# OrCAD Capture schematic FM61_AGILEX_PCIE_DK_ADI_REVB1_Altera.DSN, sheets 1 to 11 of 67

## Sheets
1 Title, Note, Rev. Hist: title: AgileX F-Series FPGA Dev Kit_ADI; rev: B1; note: M75579-100(100-0330692-B1)
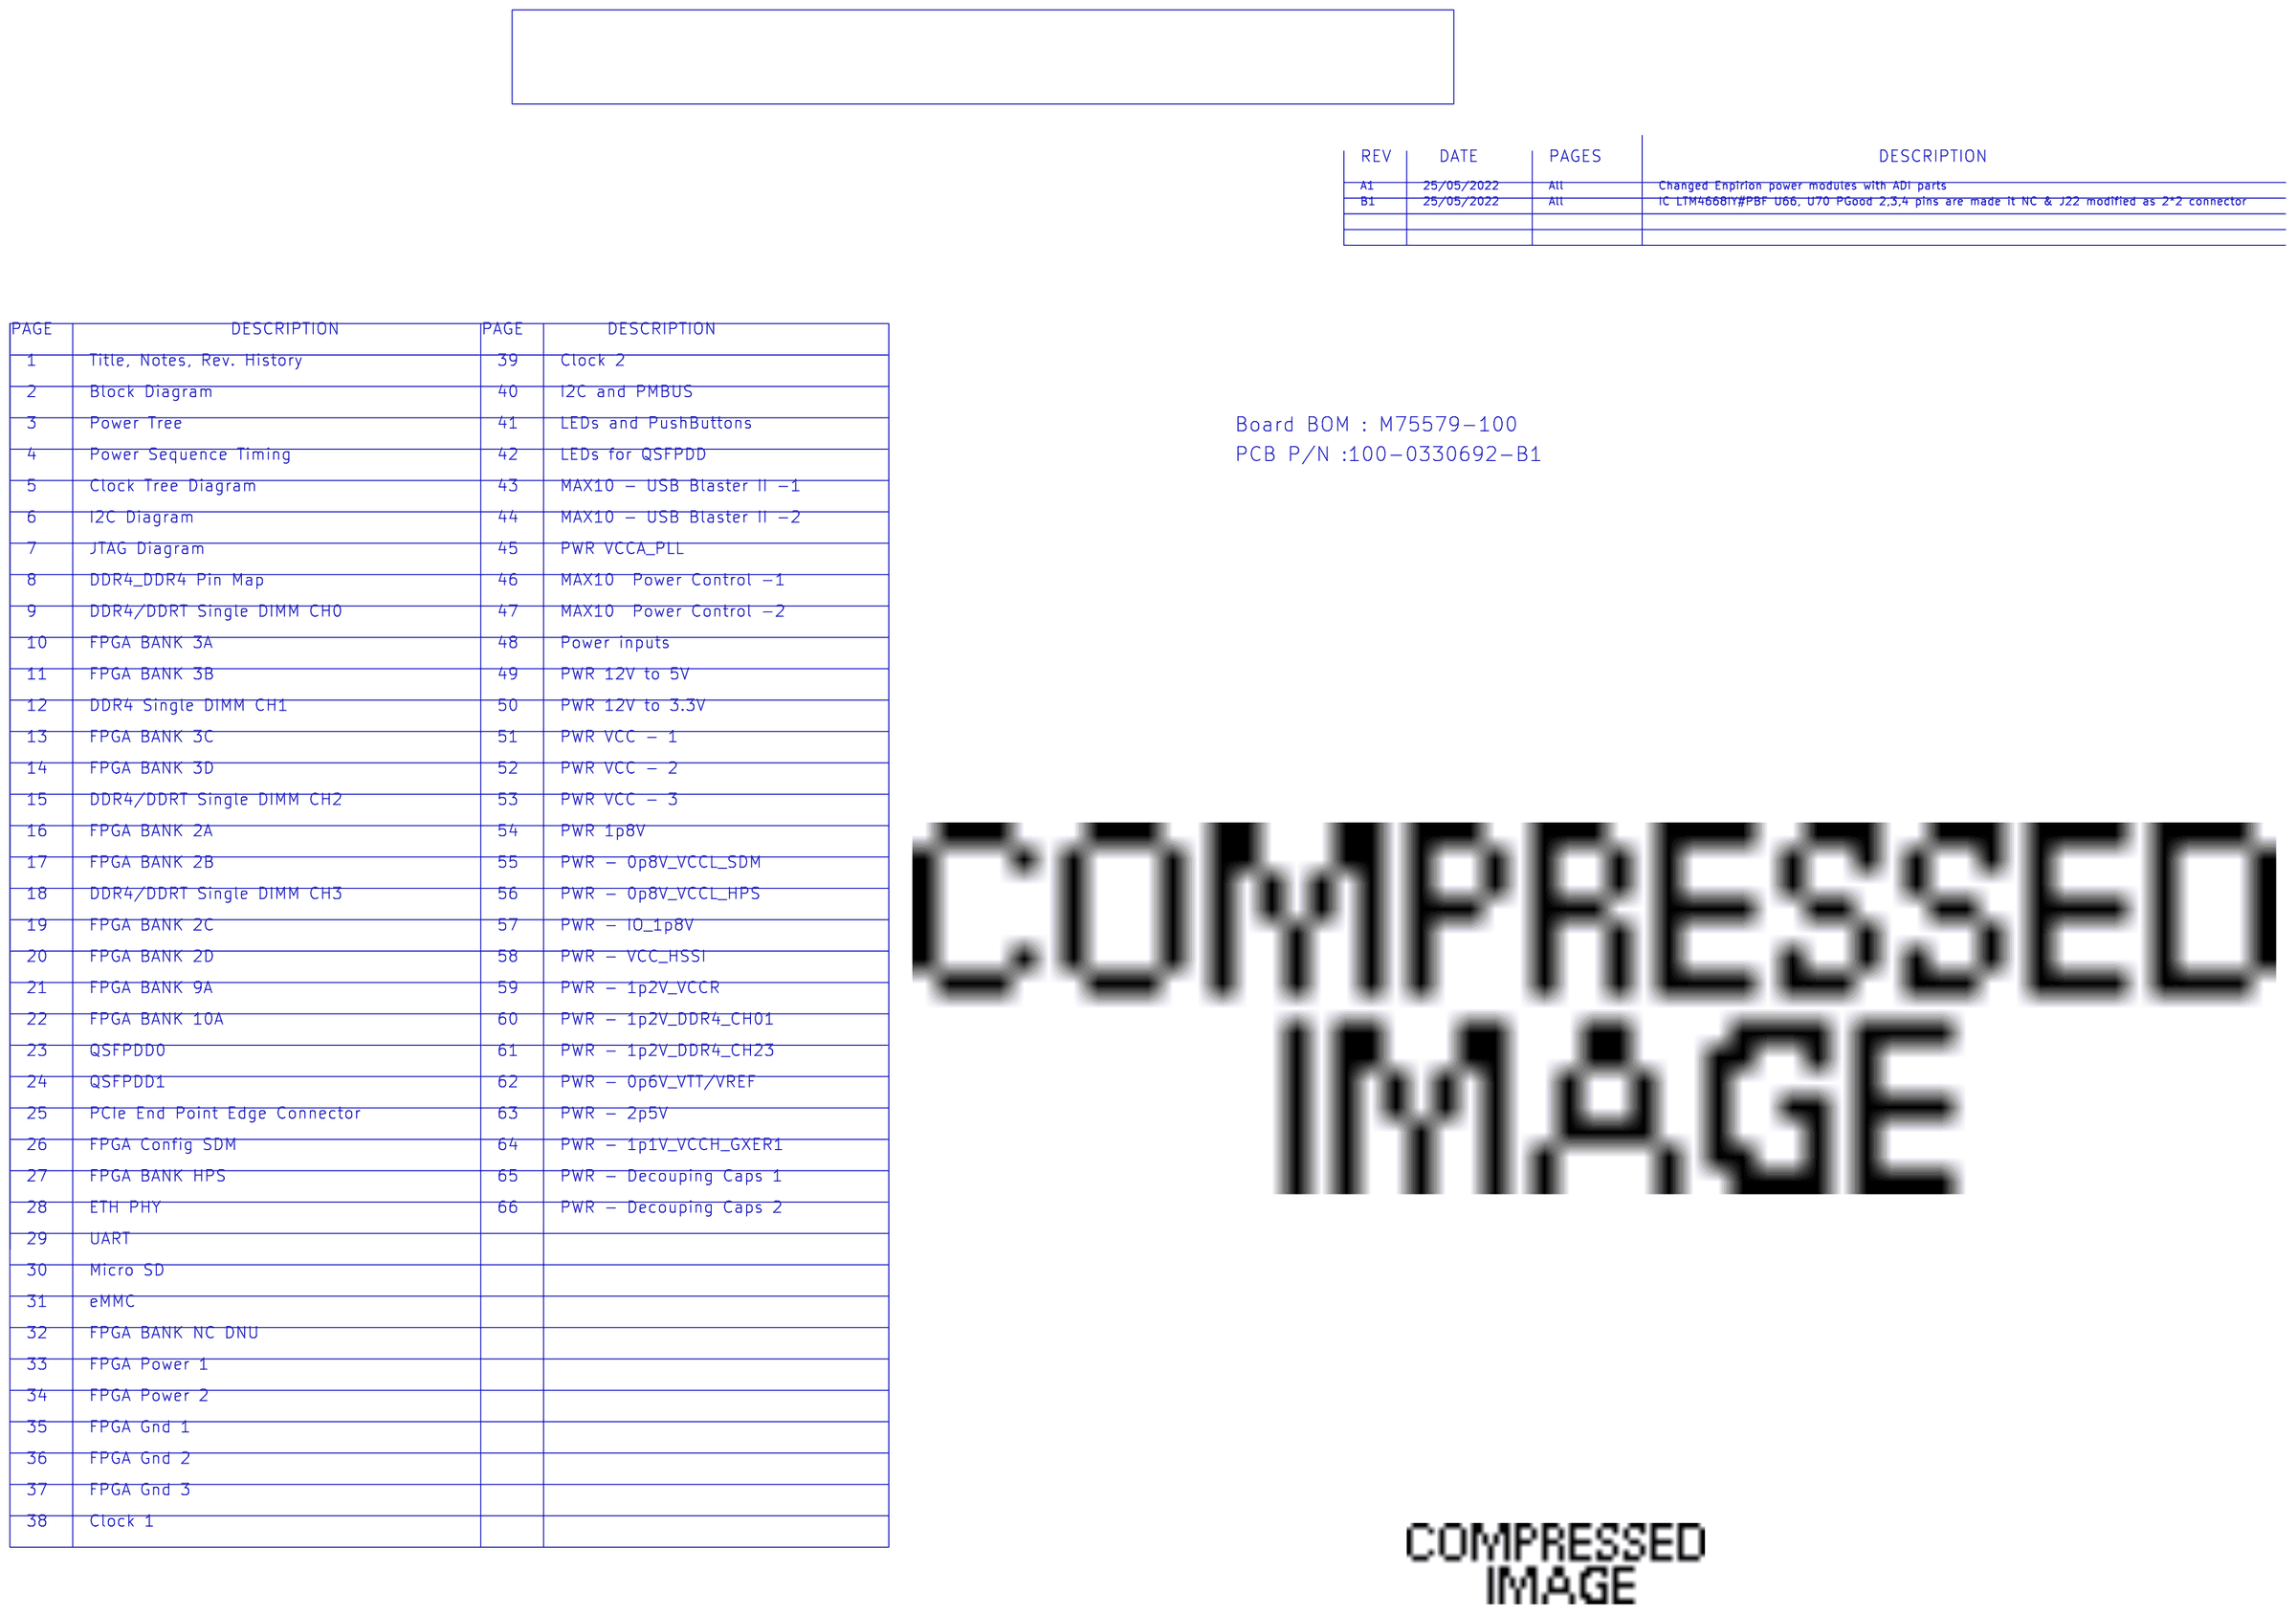
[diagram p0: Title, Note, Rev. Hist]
2 Block Diagram
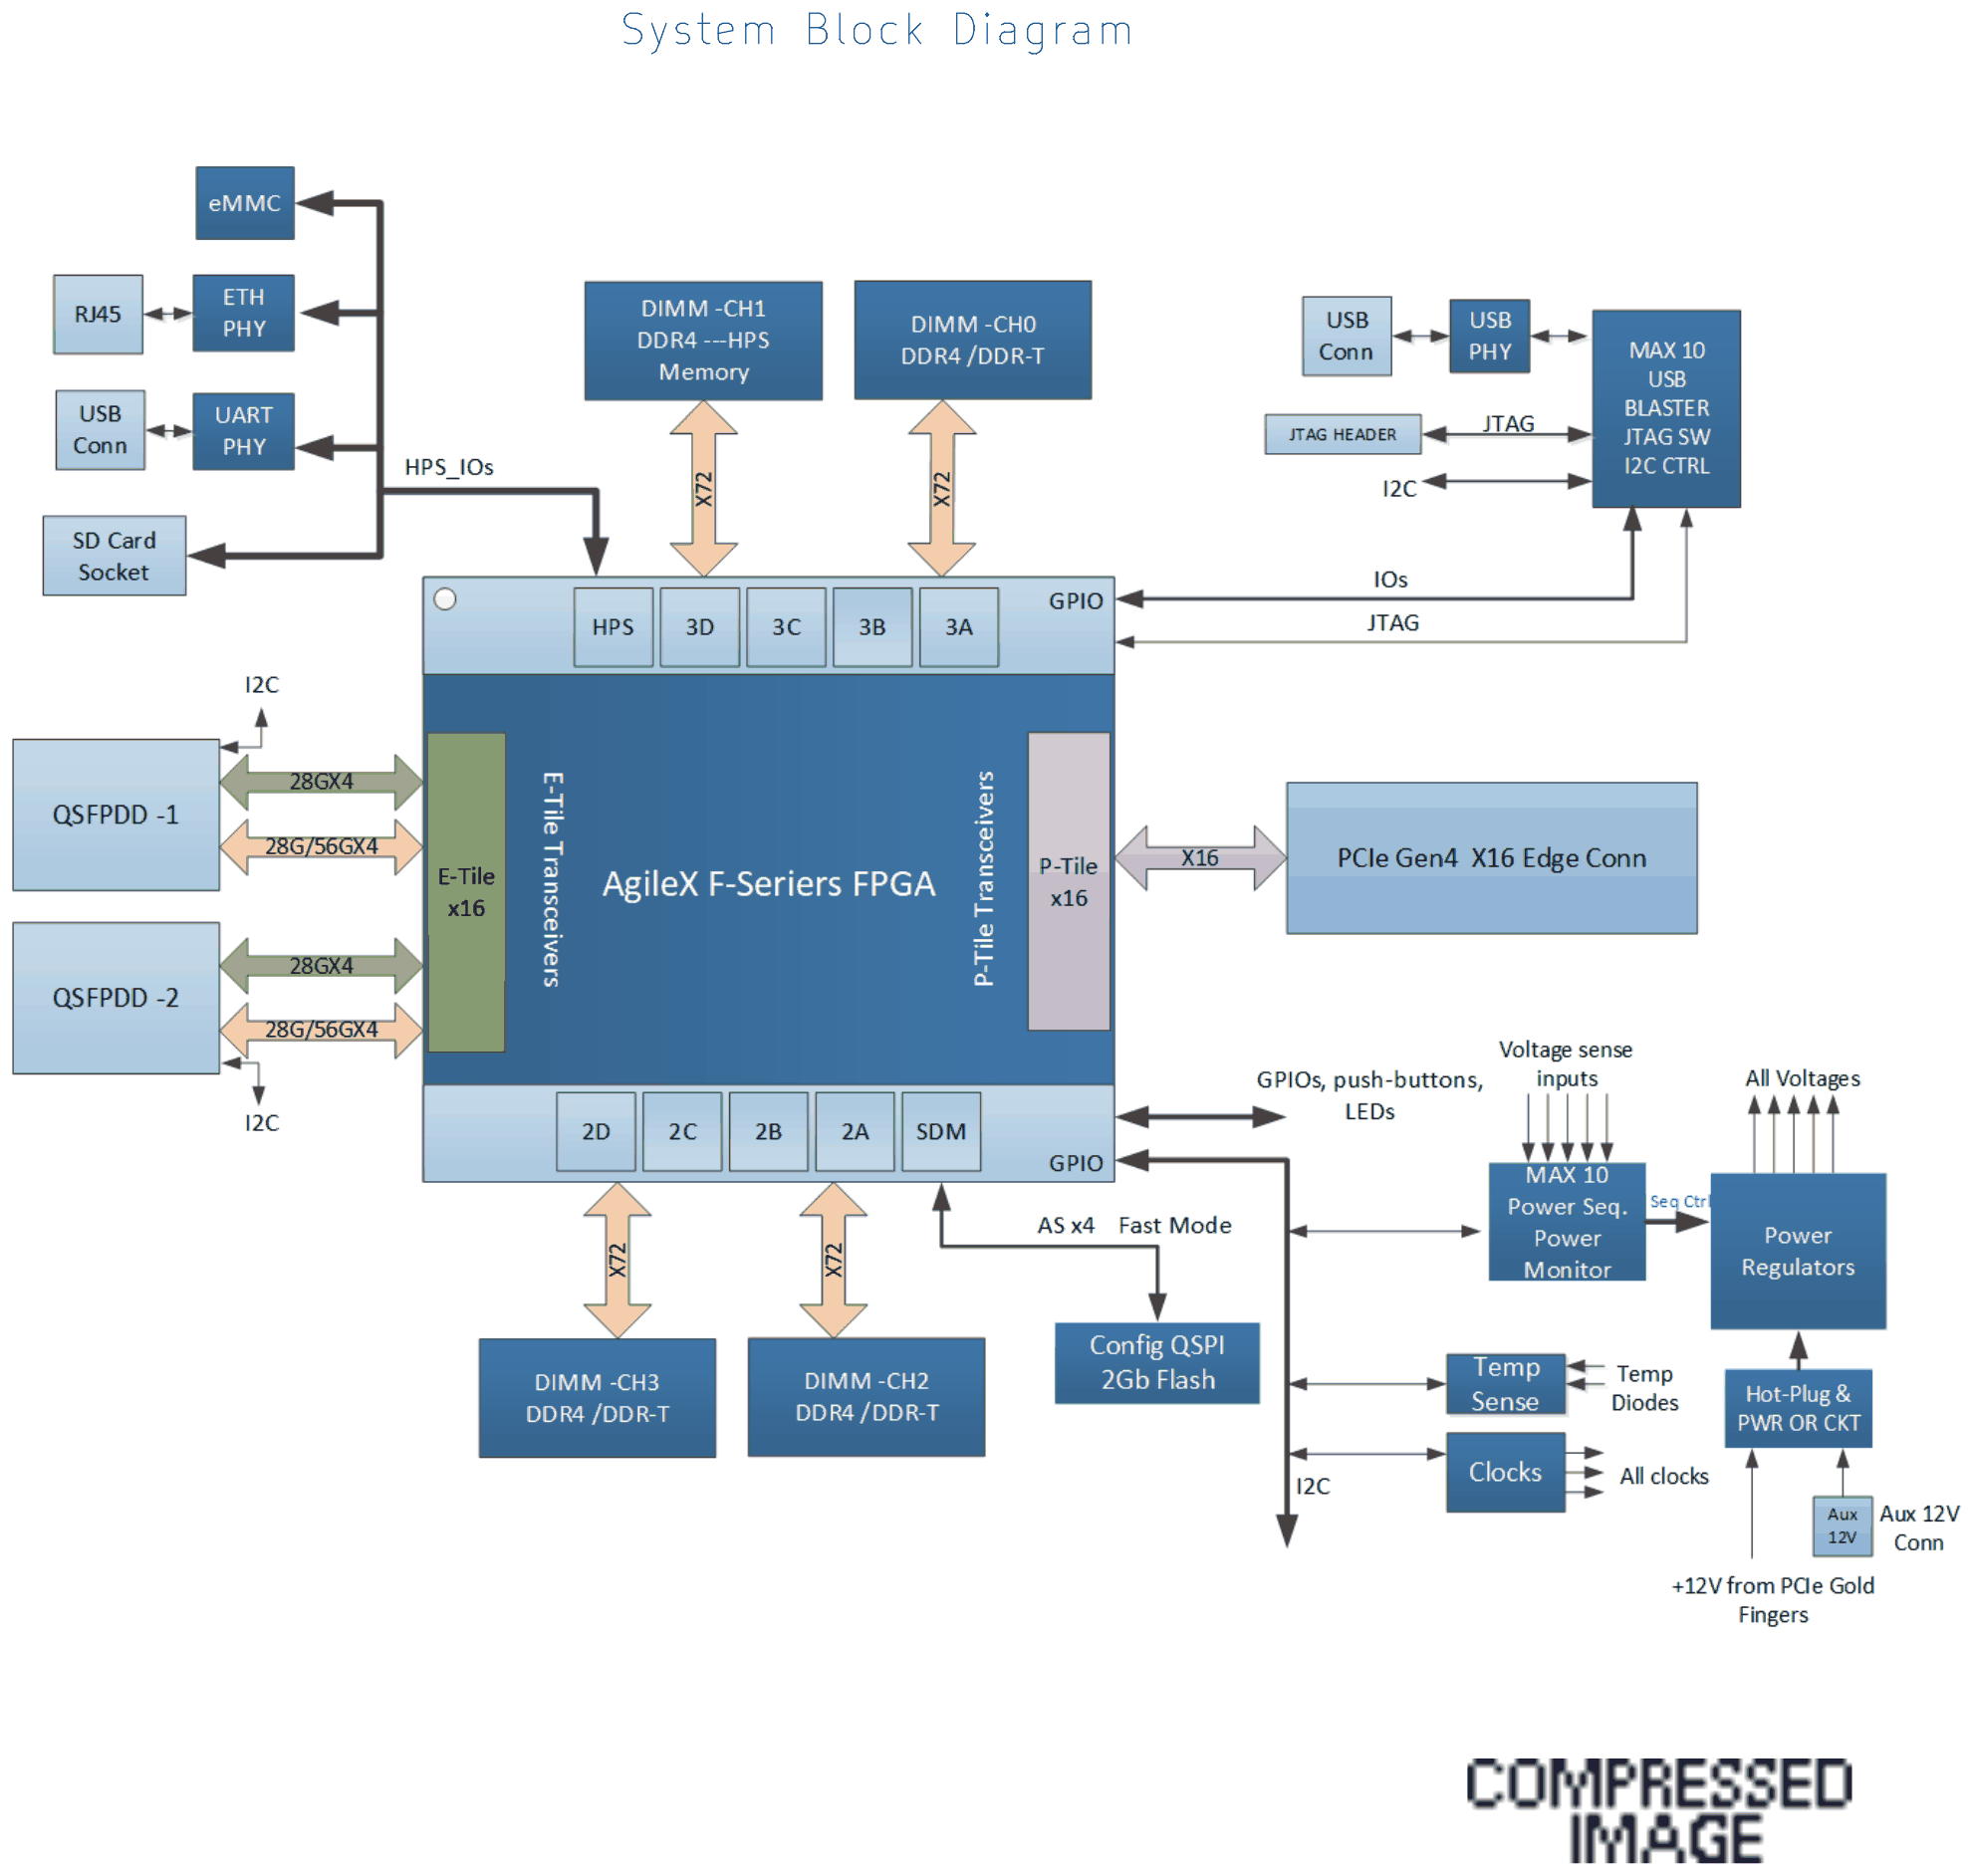
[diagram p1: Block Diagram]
3 Power Tree
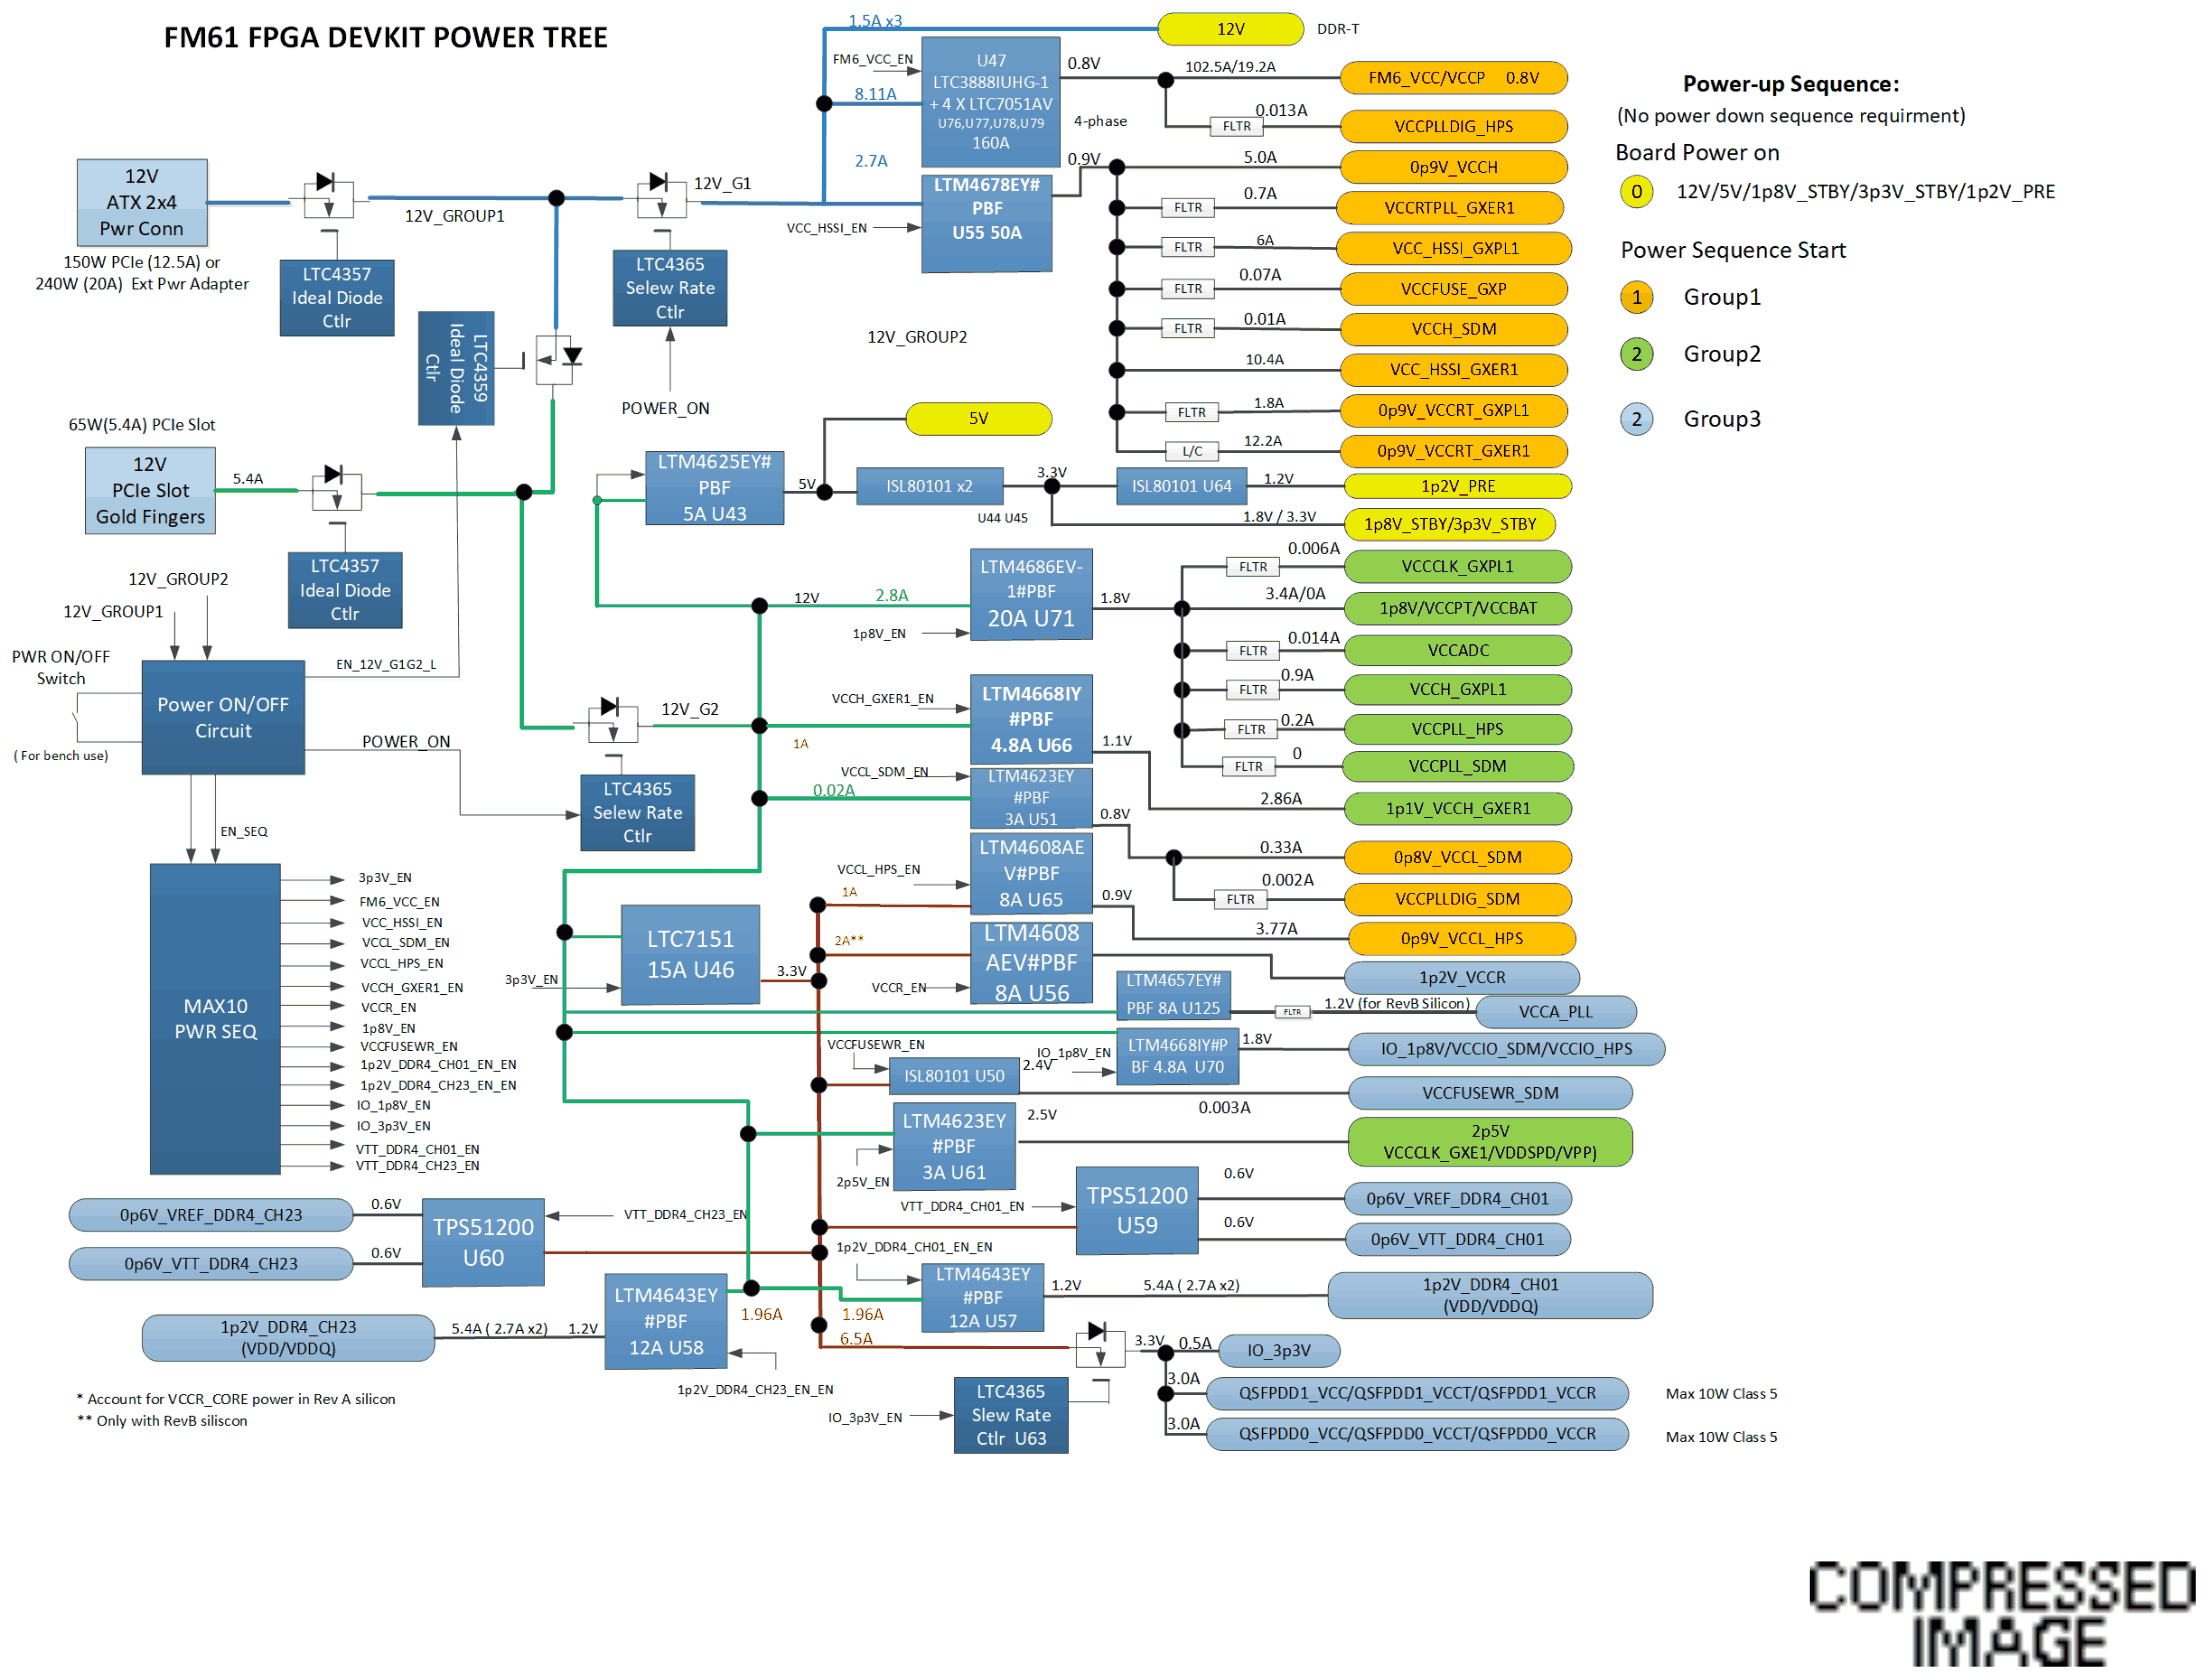
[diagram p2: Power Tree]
4 Power Sequence Timing
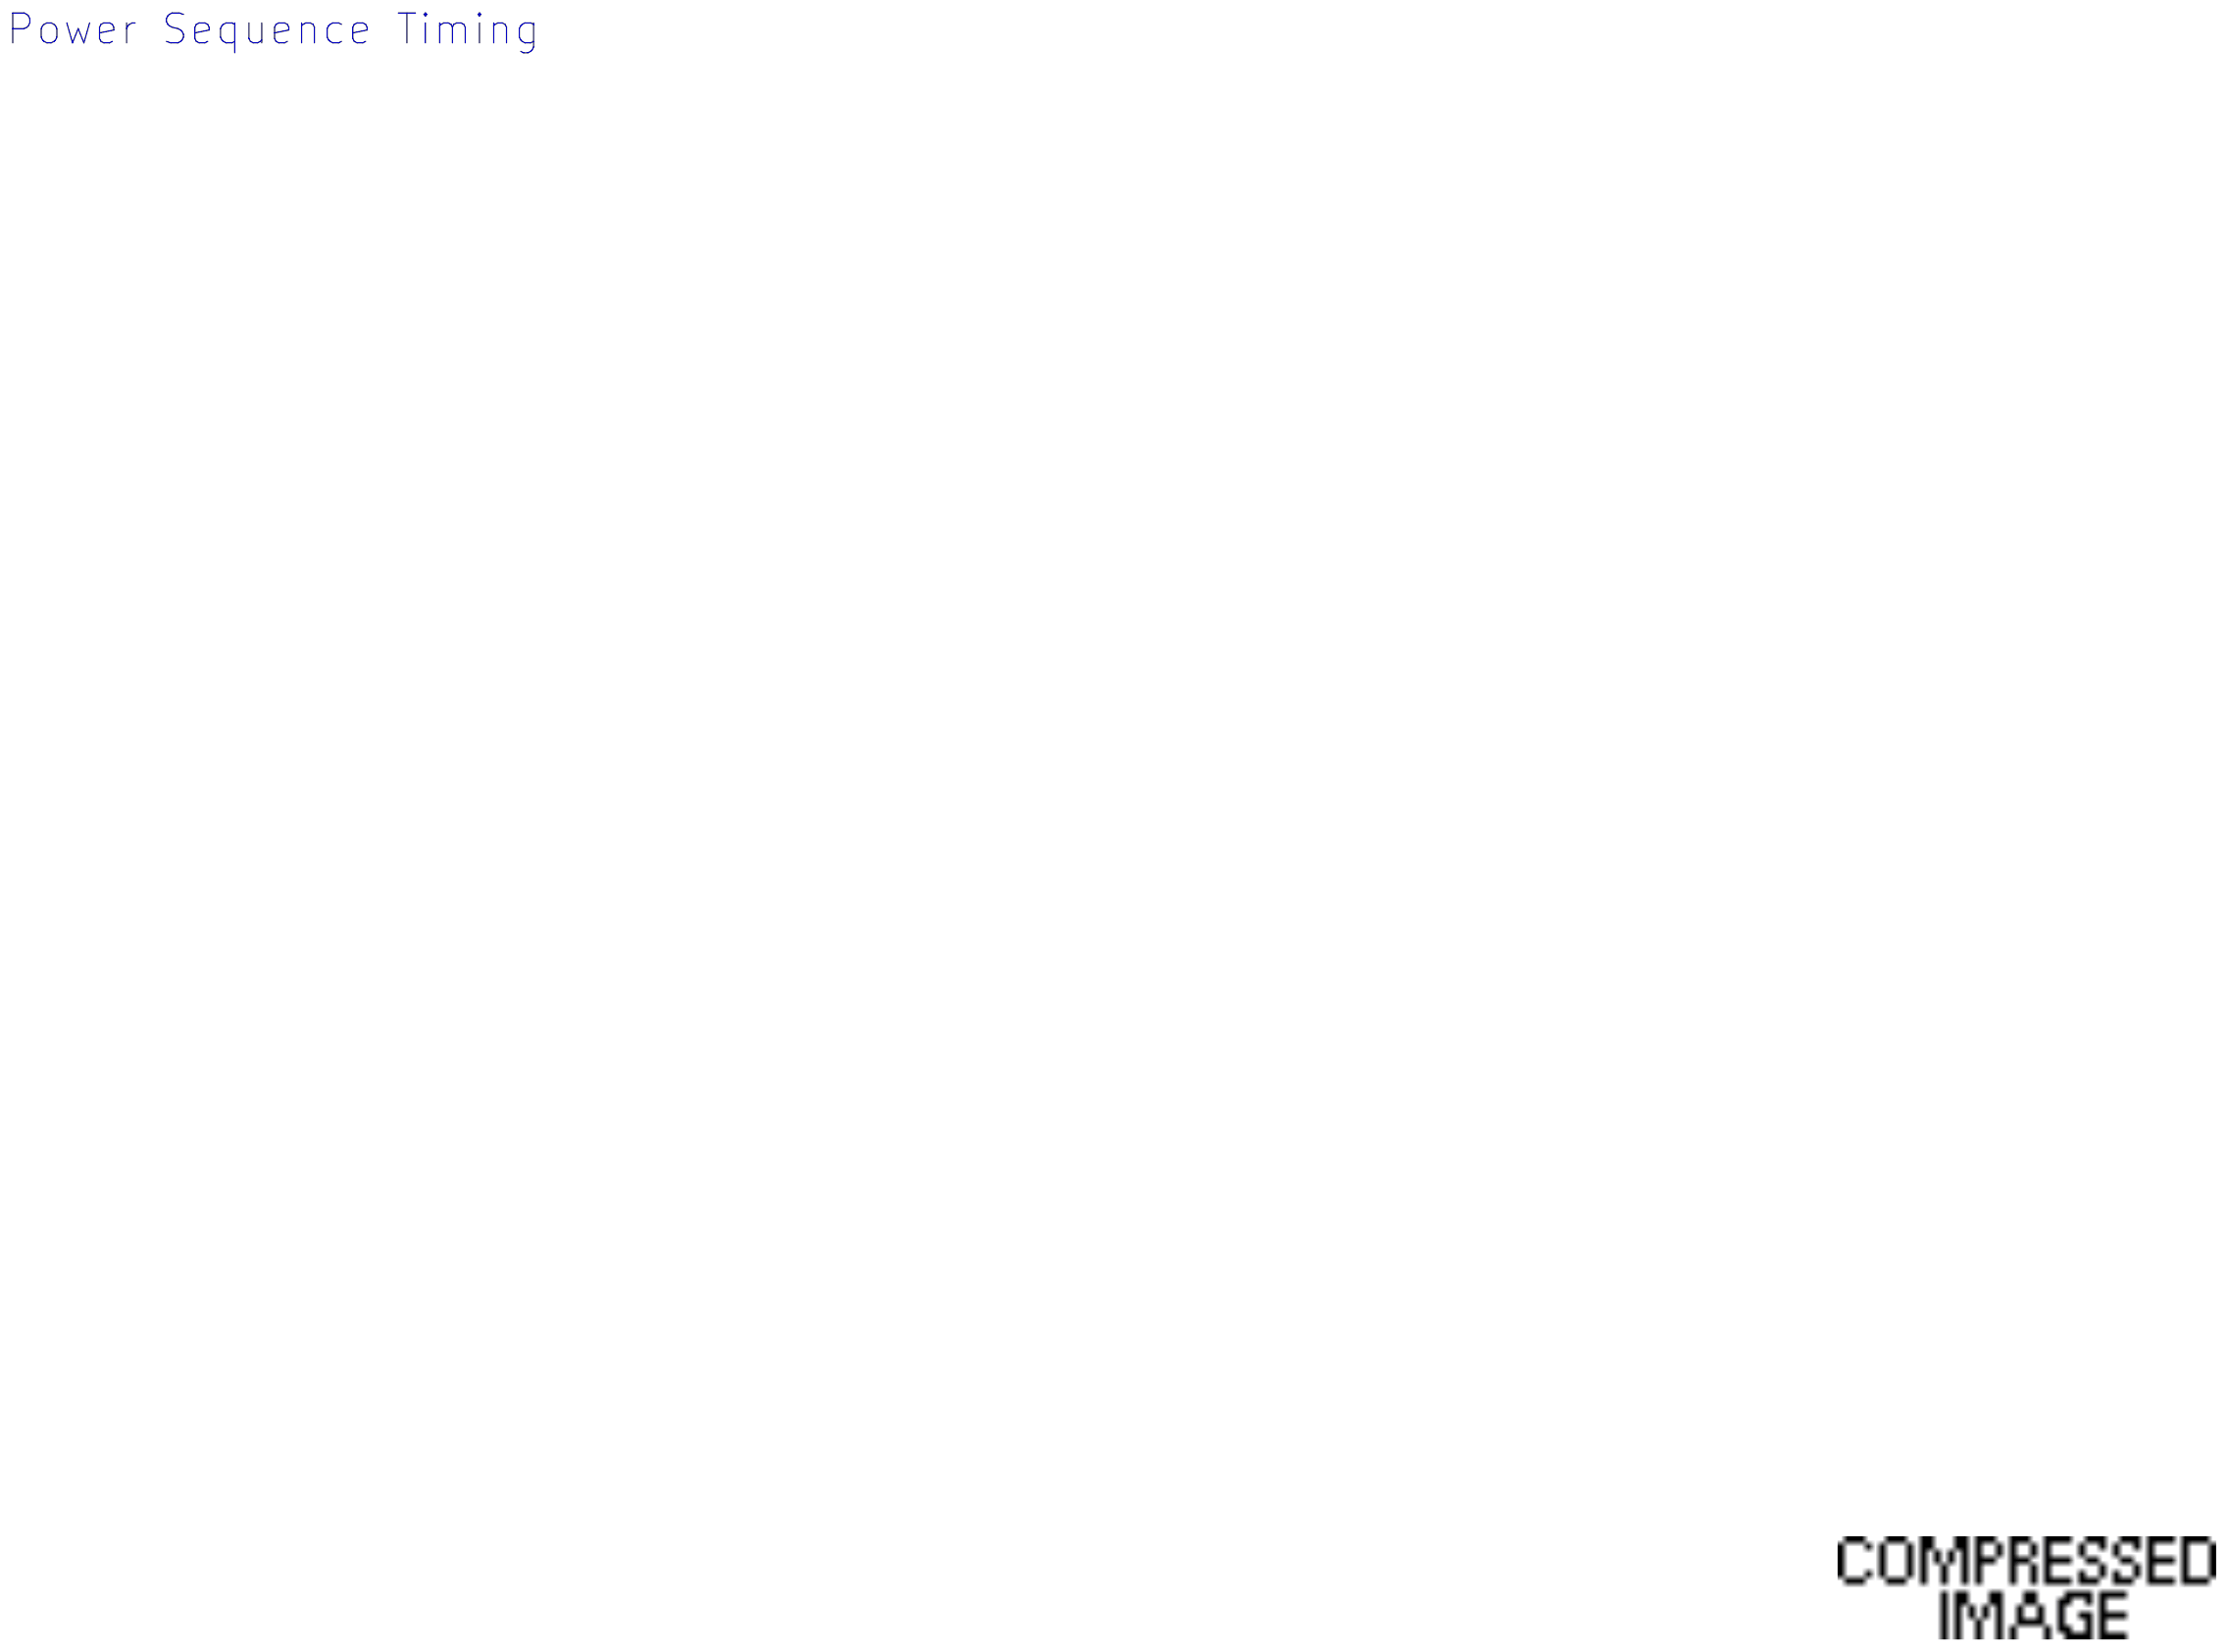
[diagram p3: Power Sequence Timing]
5 Clock Tree Diagram
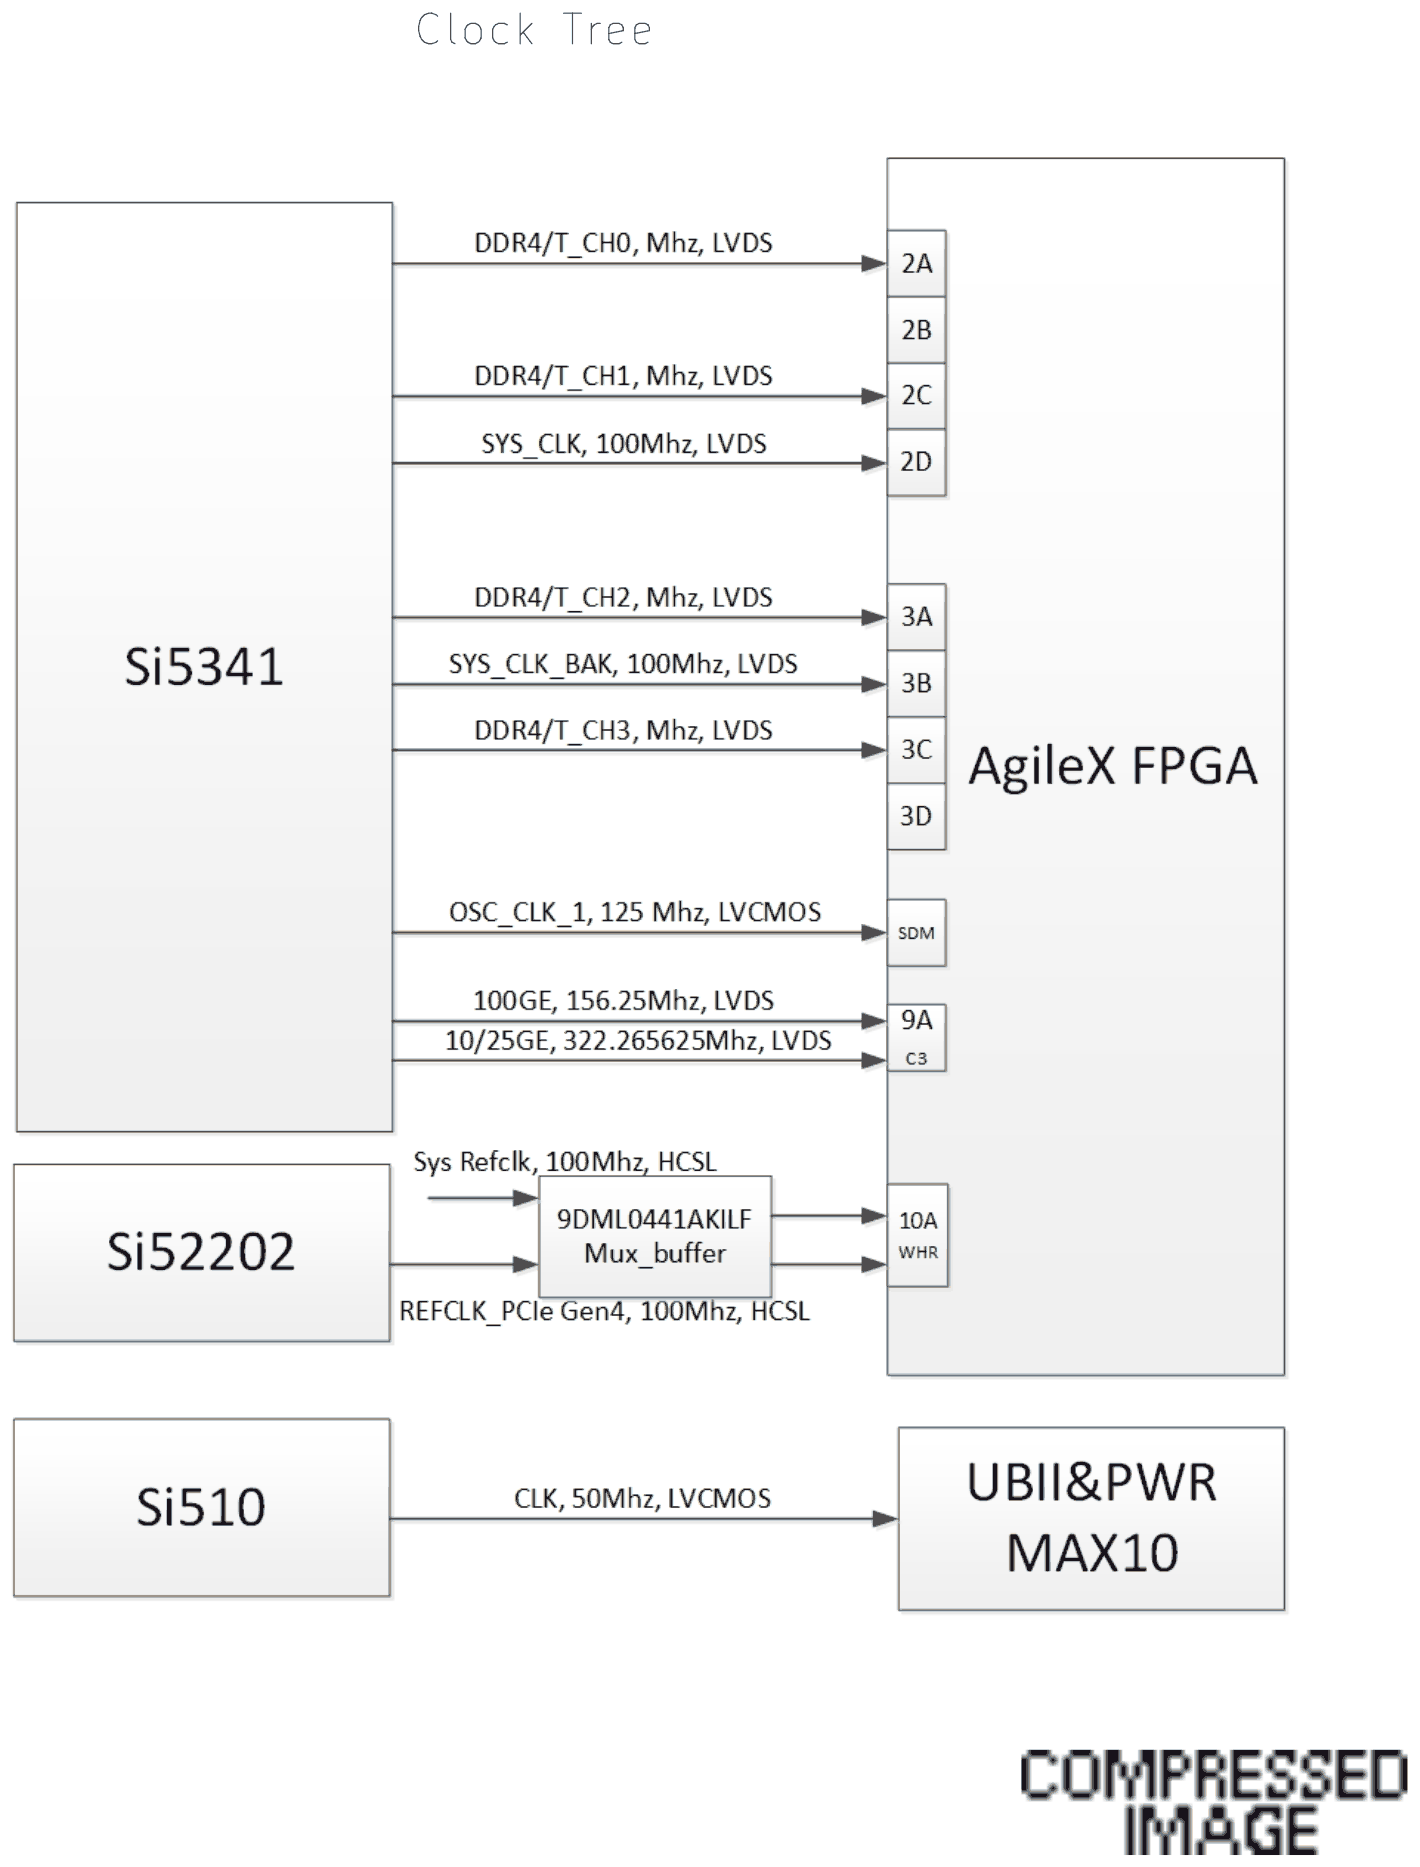
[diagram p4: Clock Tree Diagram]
6 I2C Diagram
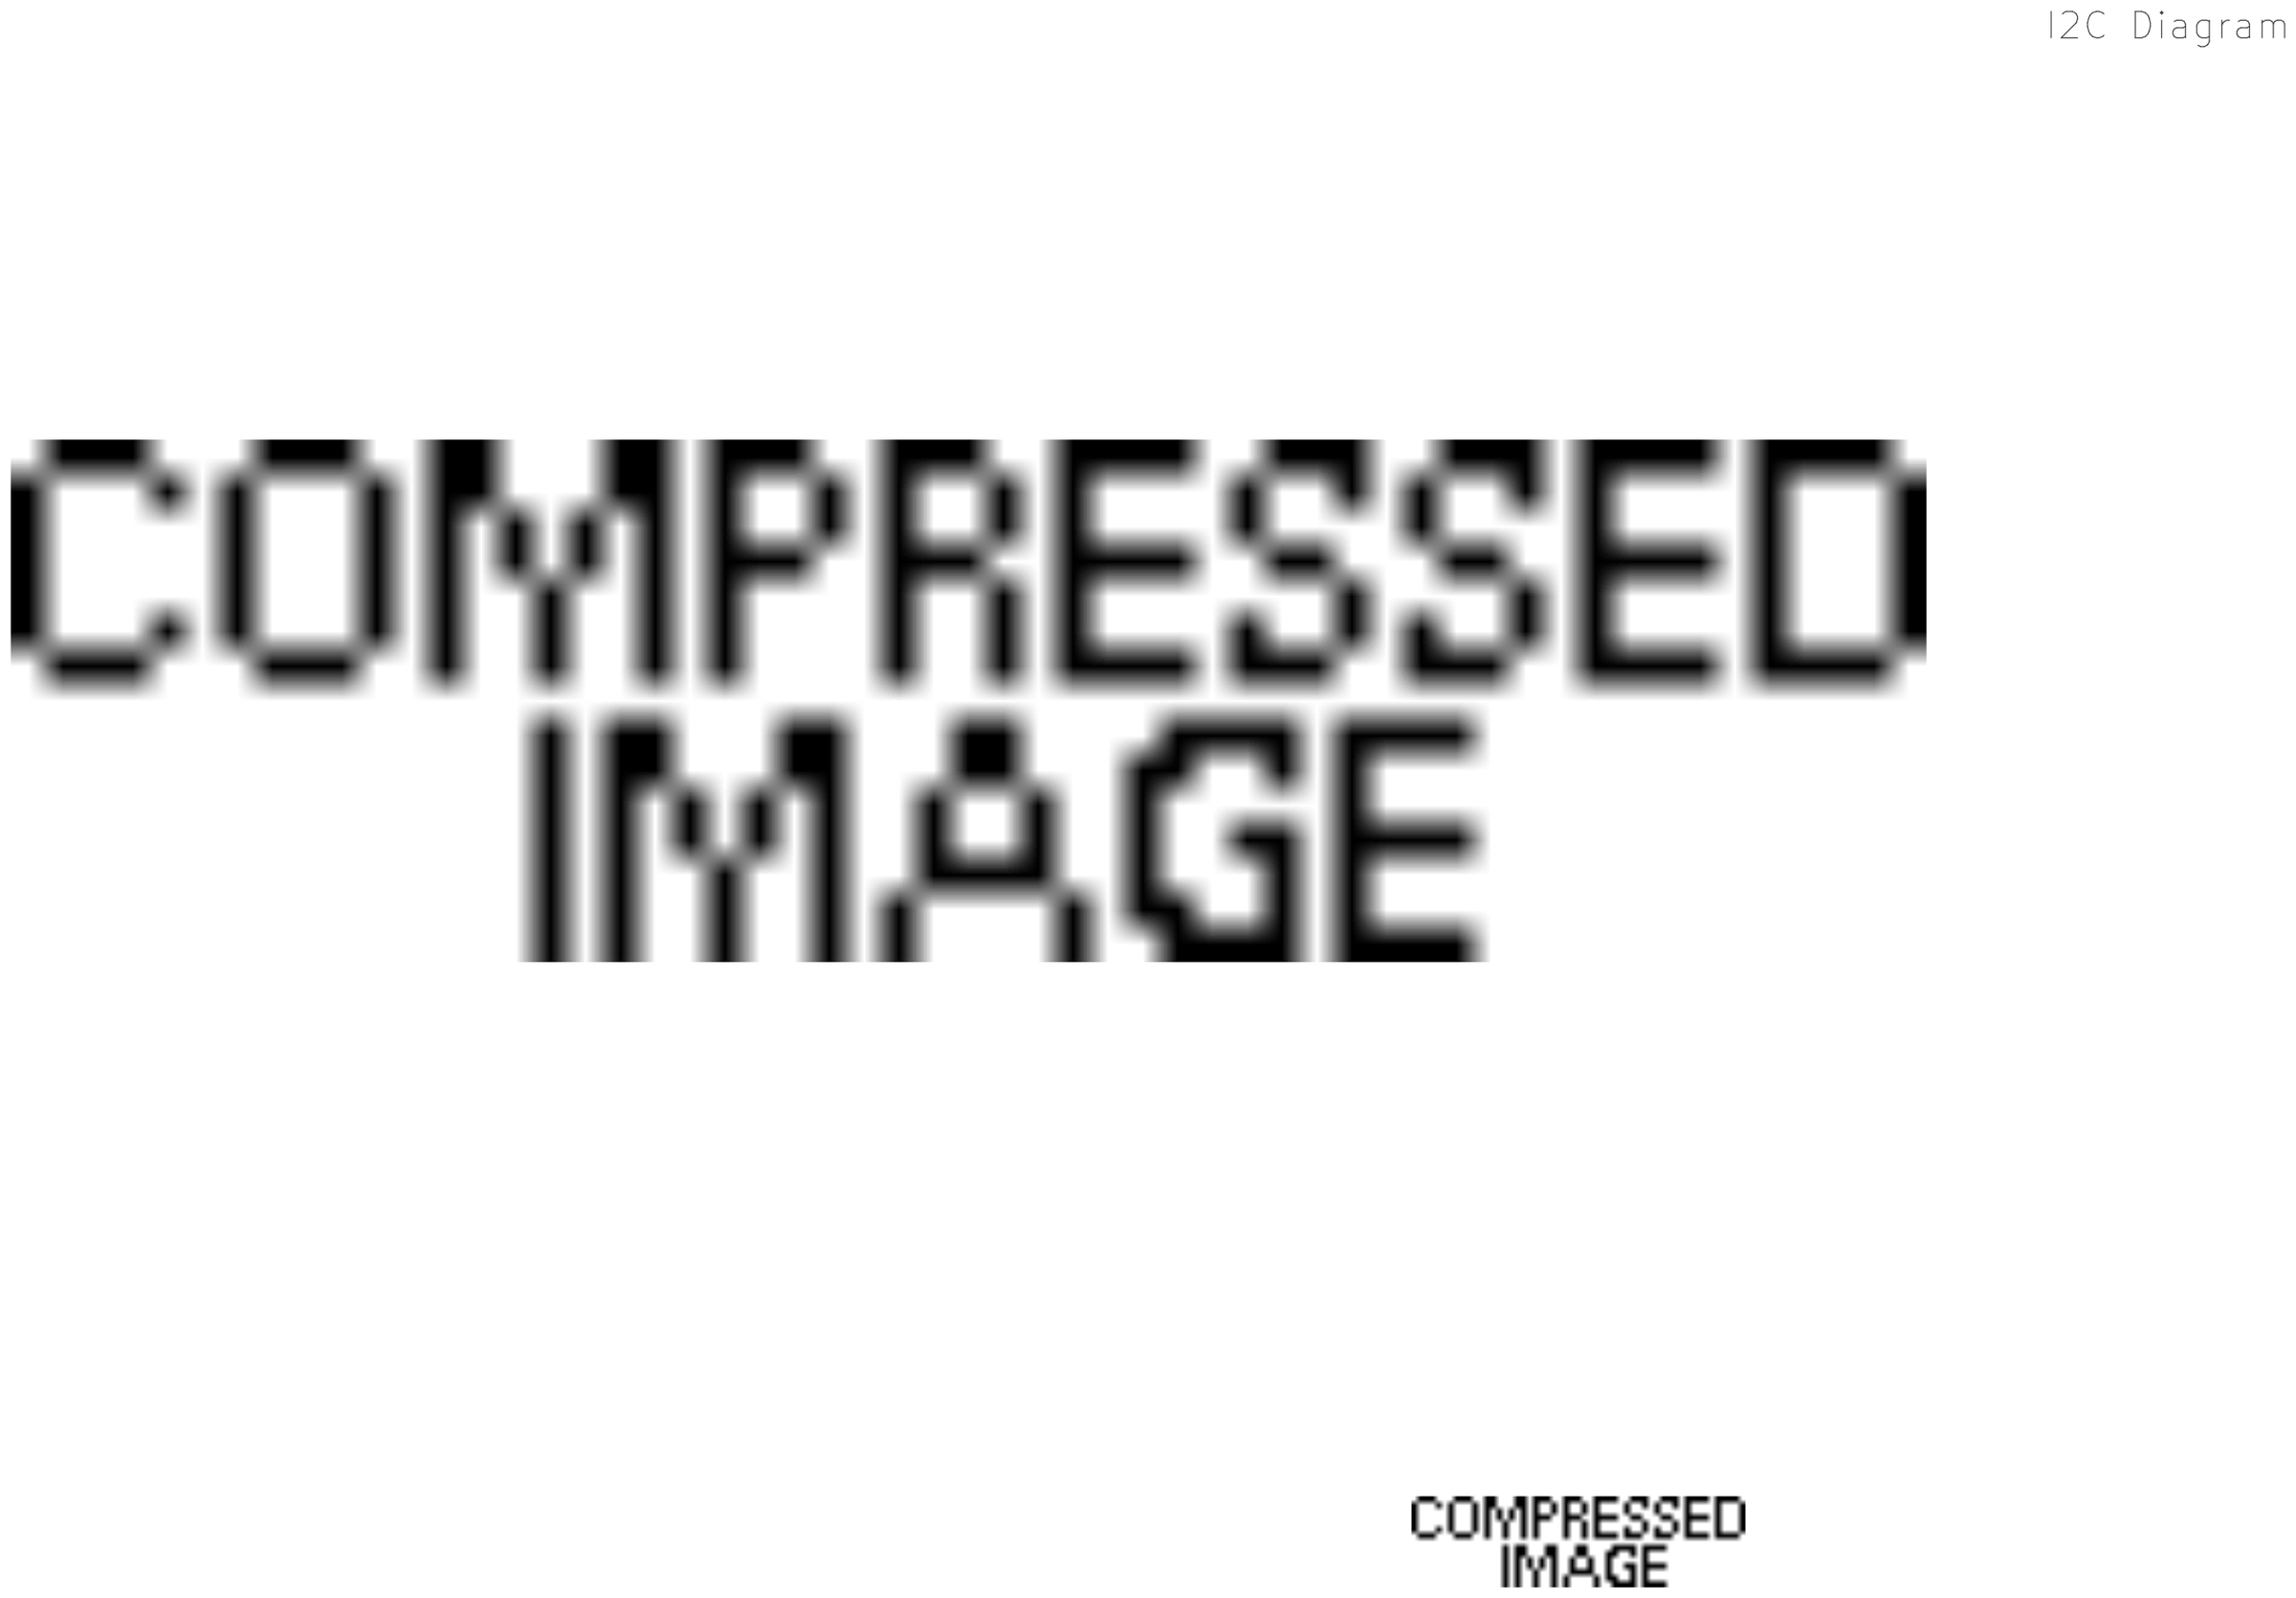
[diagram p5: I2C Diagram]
7 JTAG Diagram
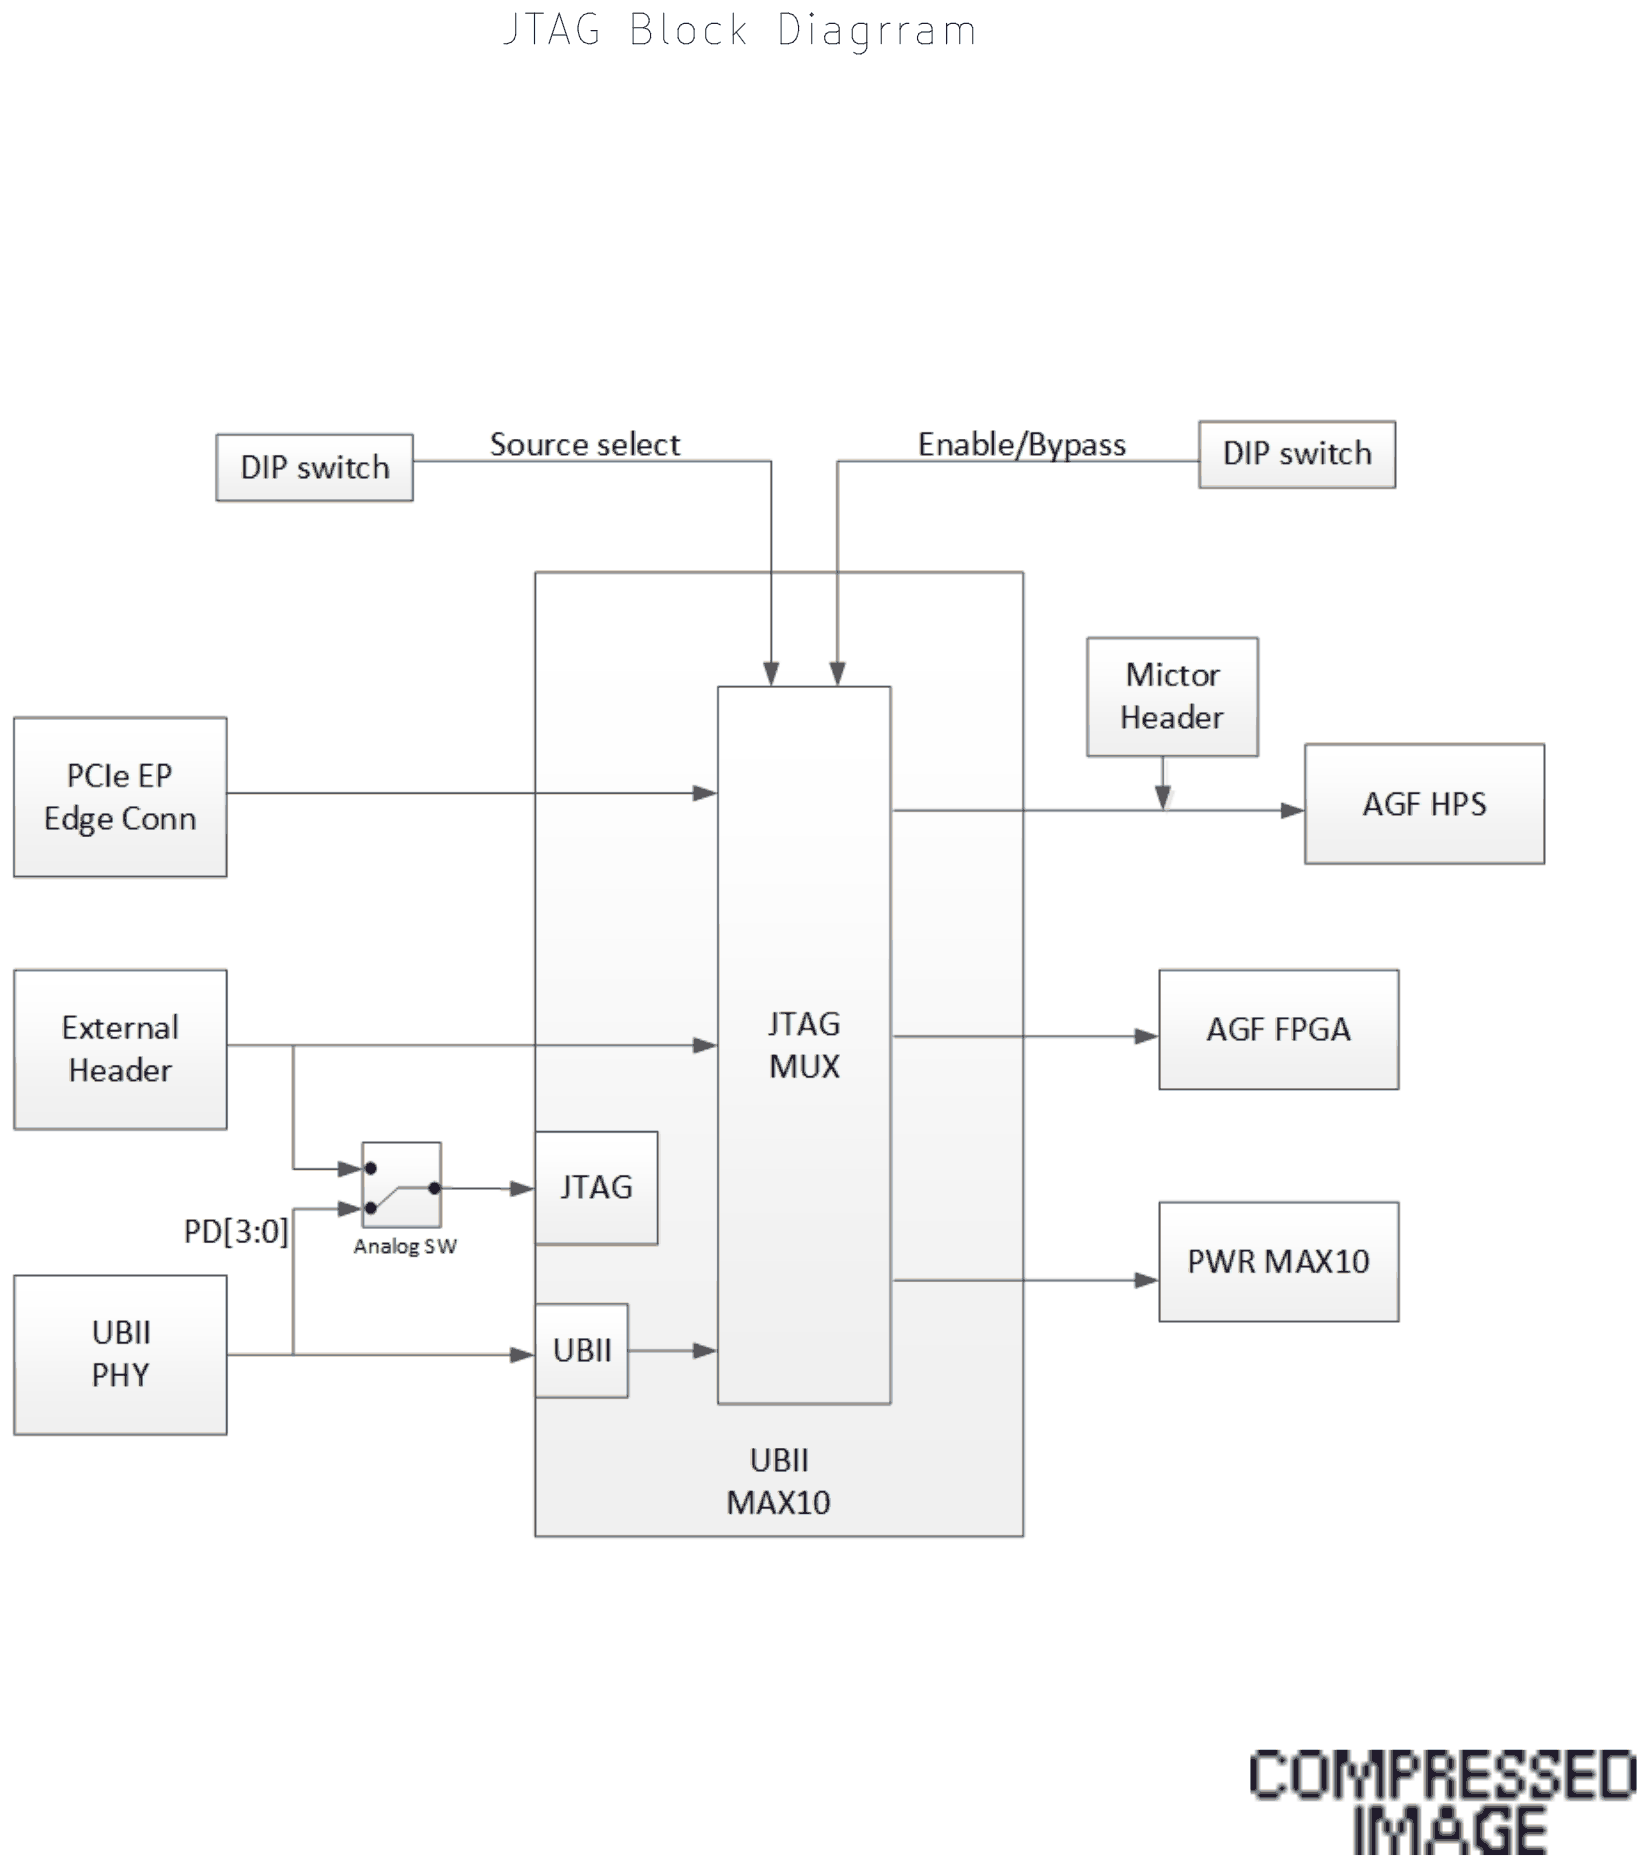
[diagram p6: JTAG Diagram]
8 DDR4_DDRT Pin Map
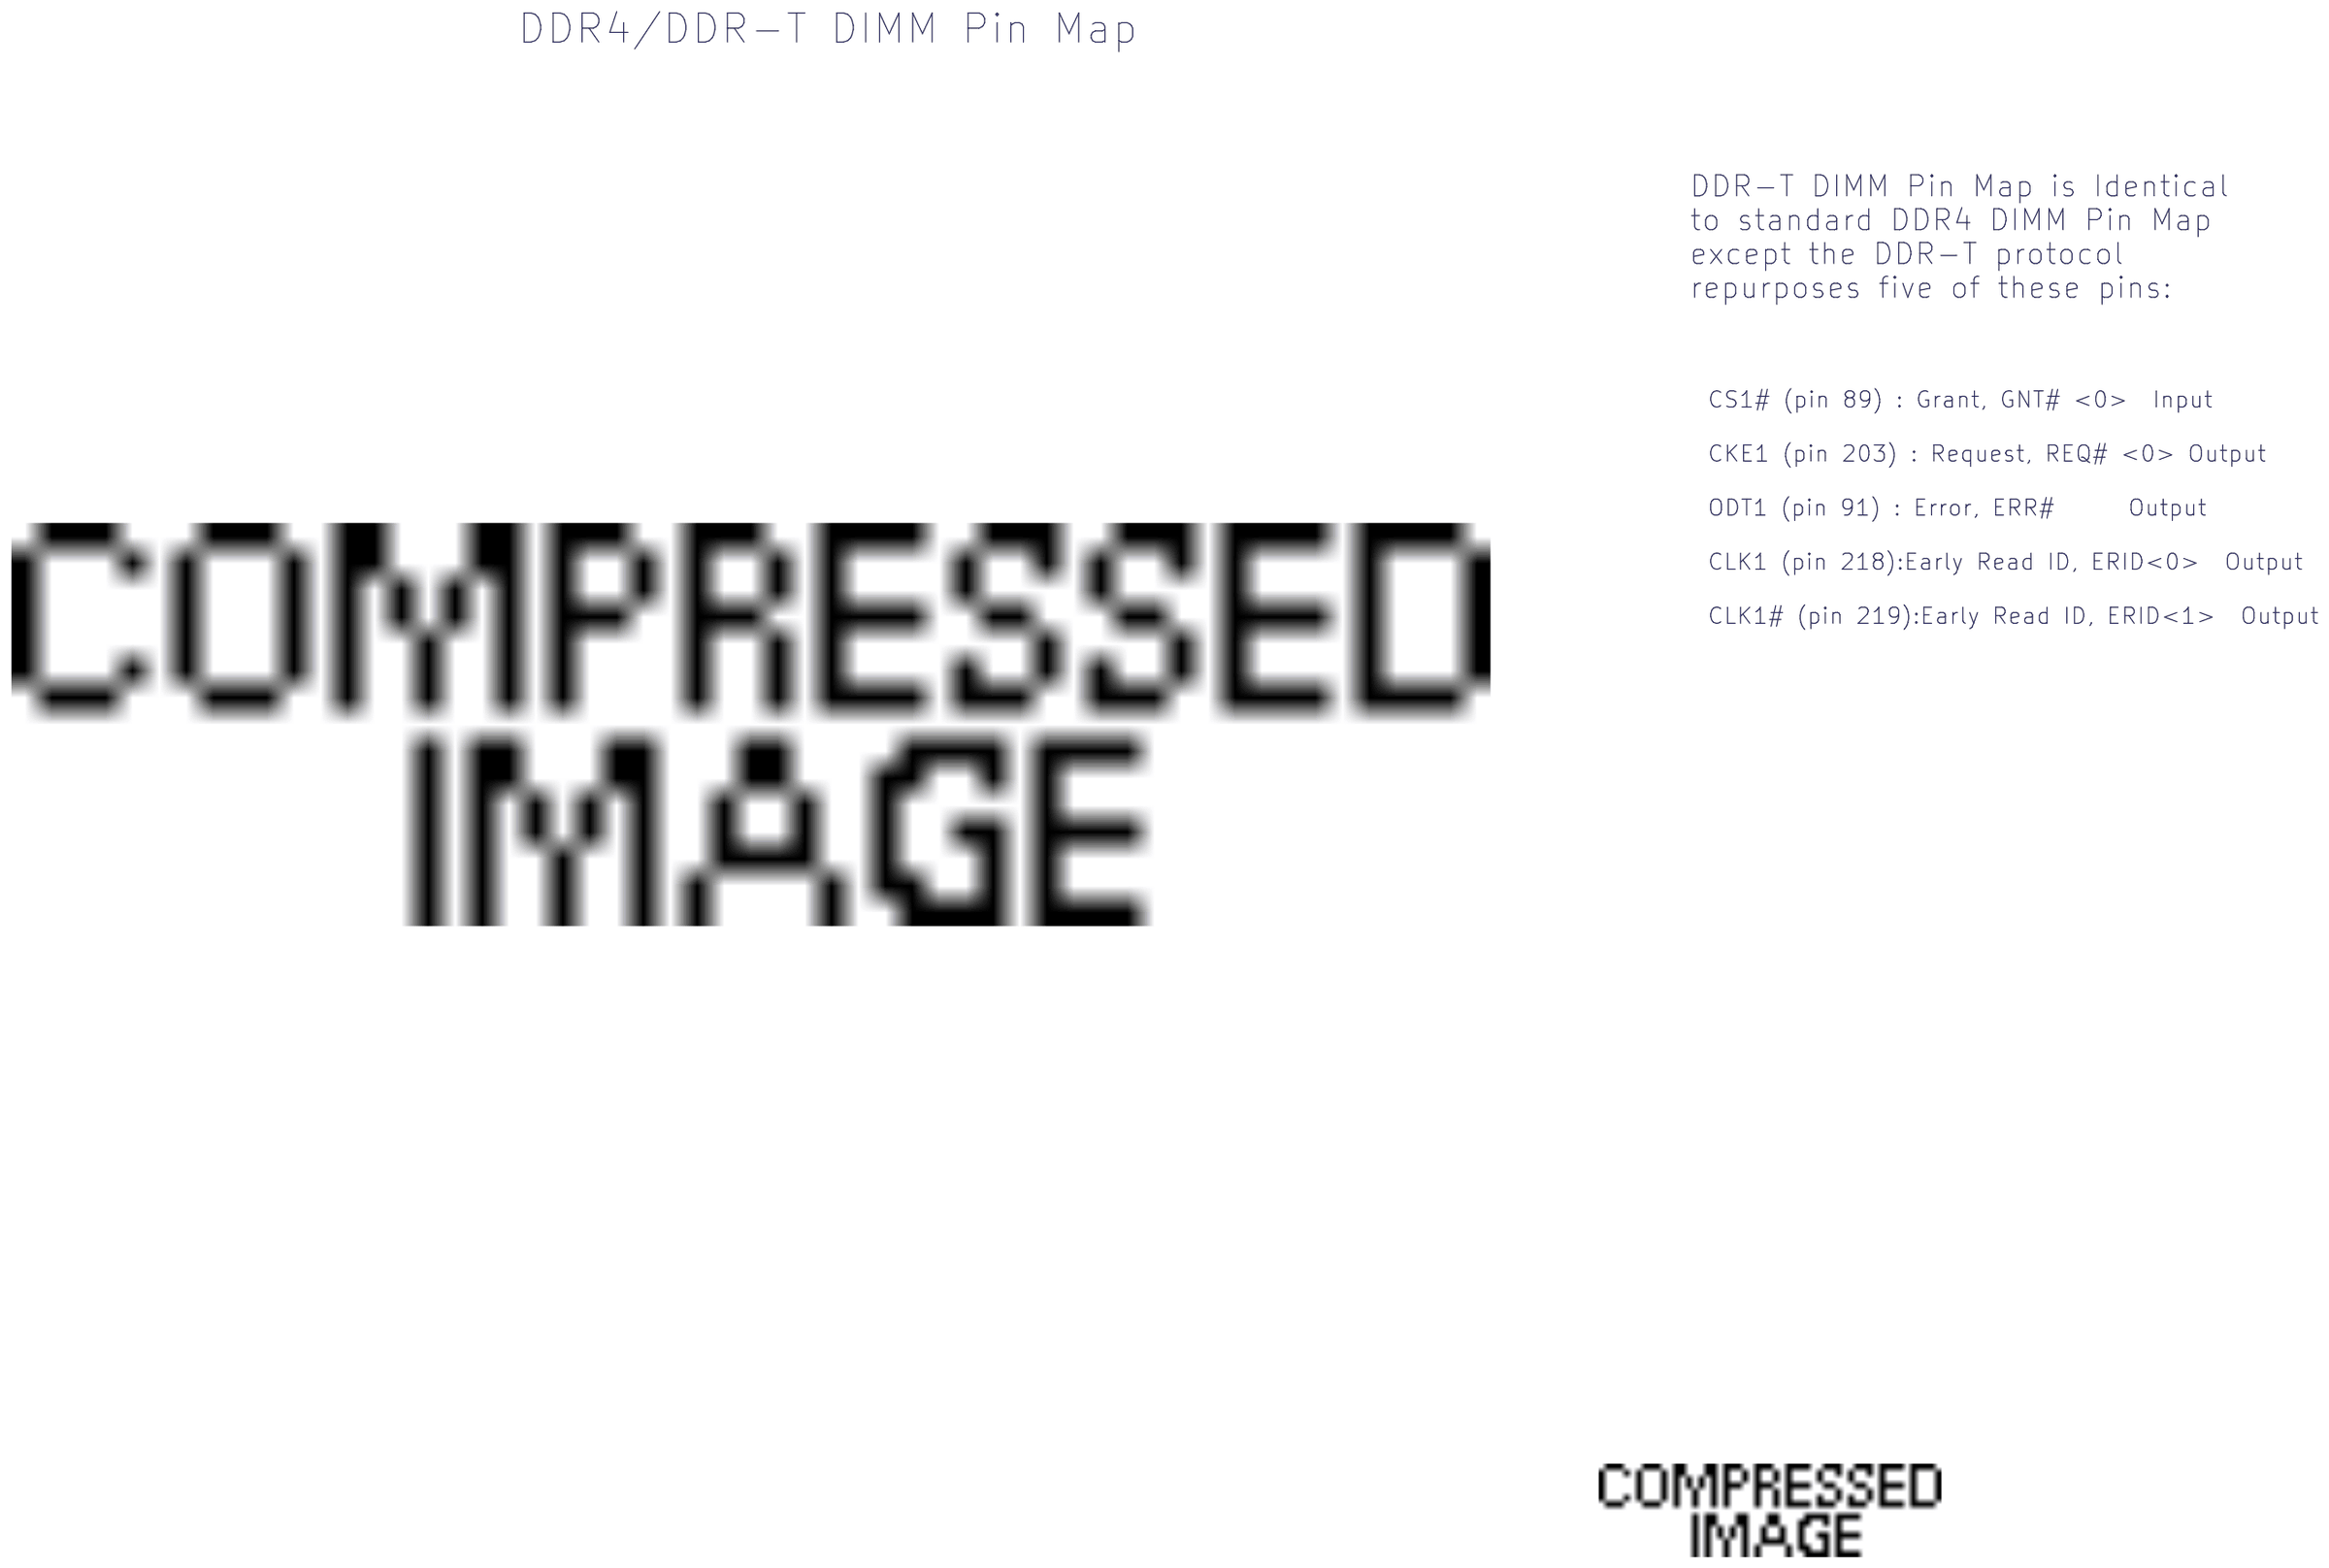
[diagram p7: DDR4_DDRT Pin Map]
9 DDR4/DDRT Single DIMM CH0: size B
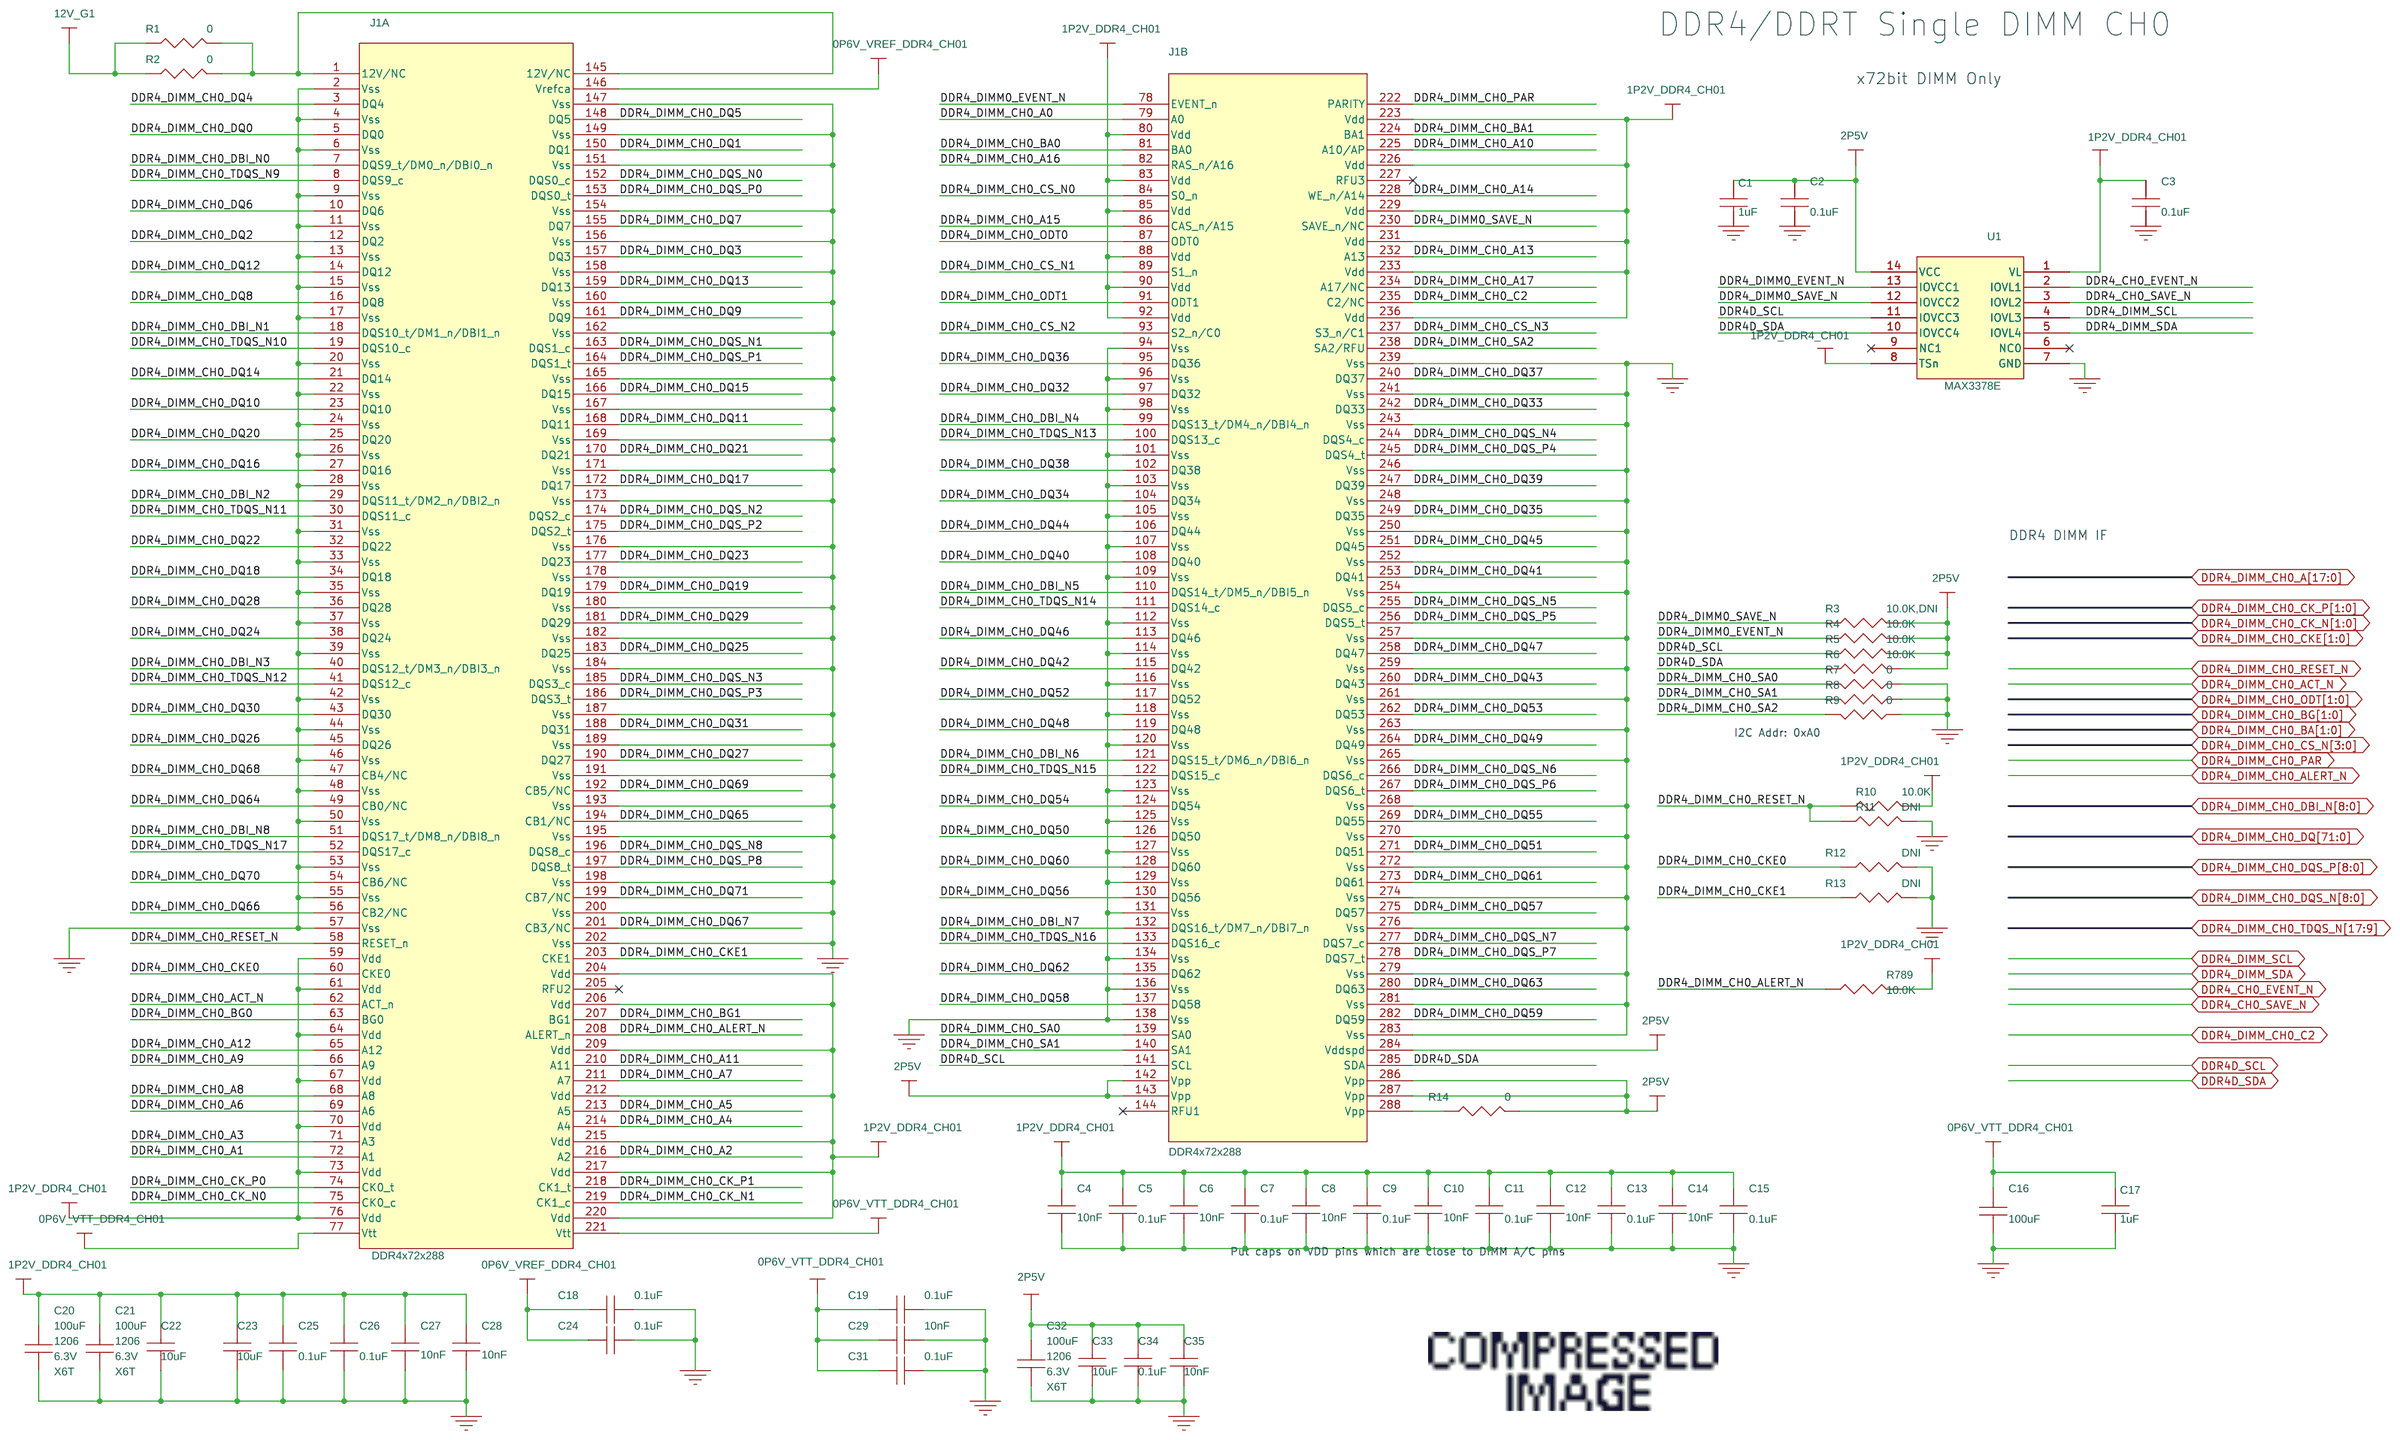
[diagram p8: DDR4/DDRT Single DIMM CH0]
10 FPGA BANK 3A: size B
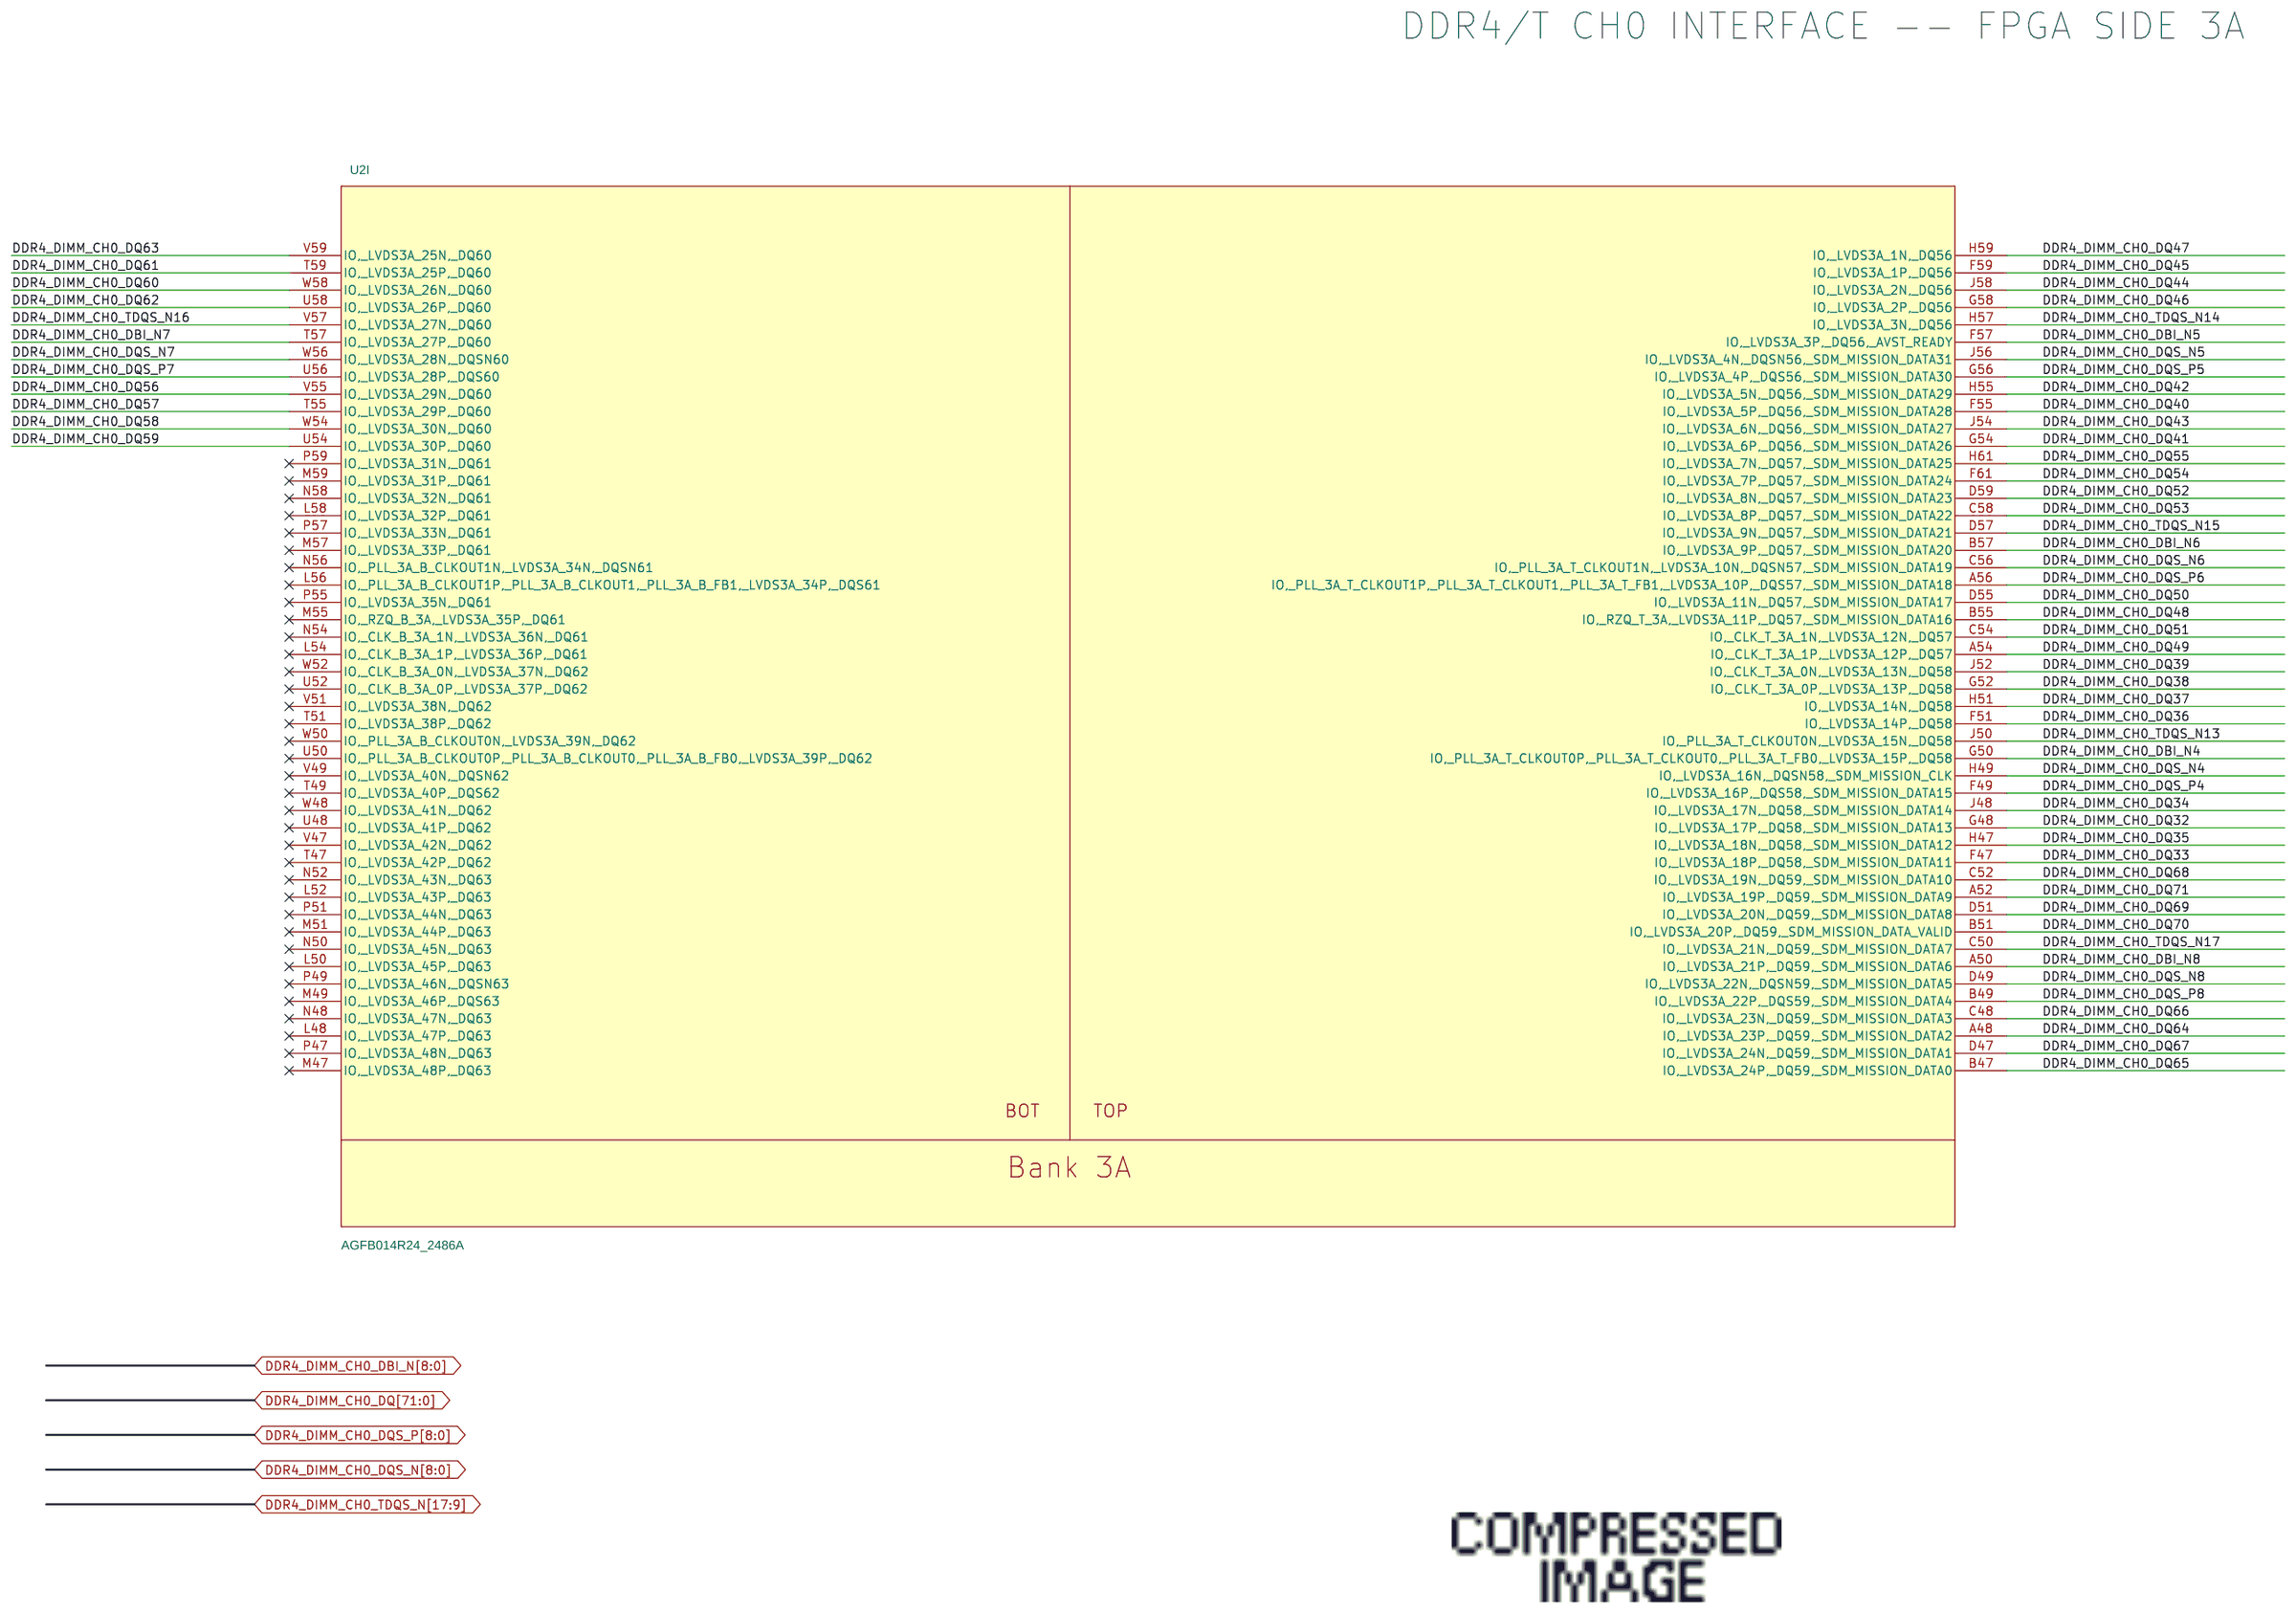
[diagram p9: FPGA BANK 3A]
11 FPGA BANK 3B: size B
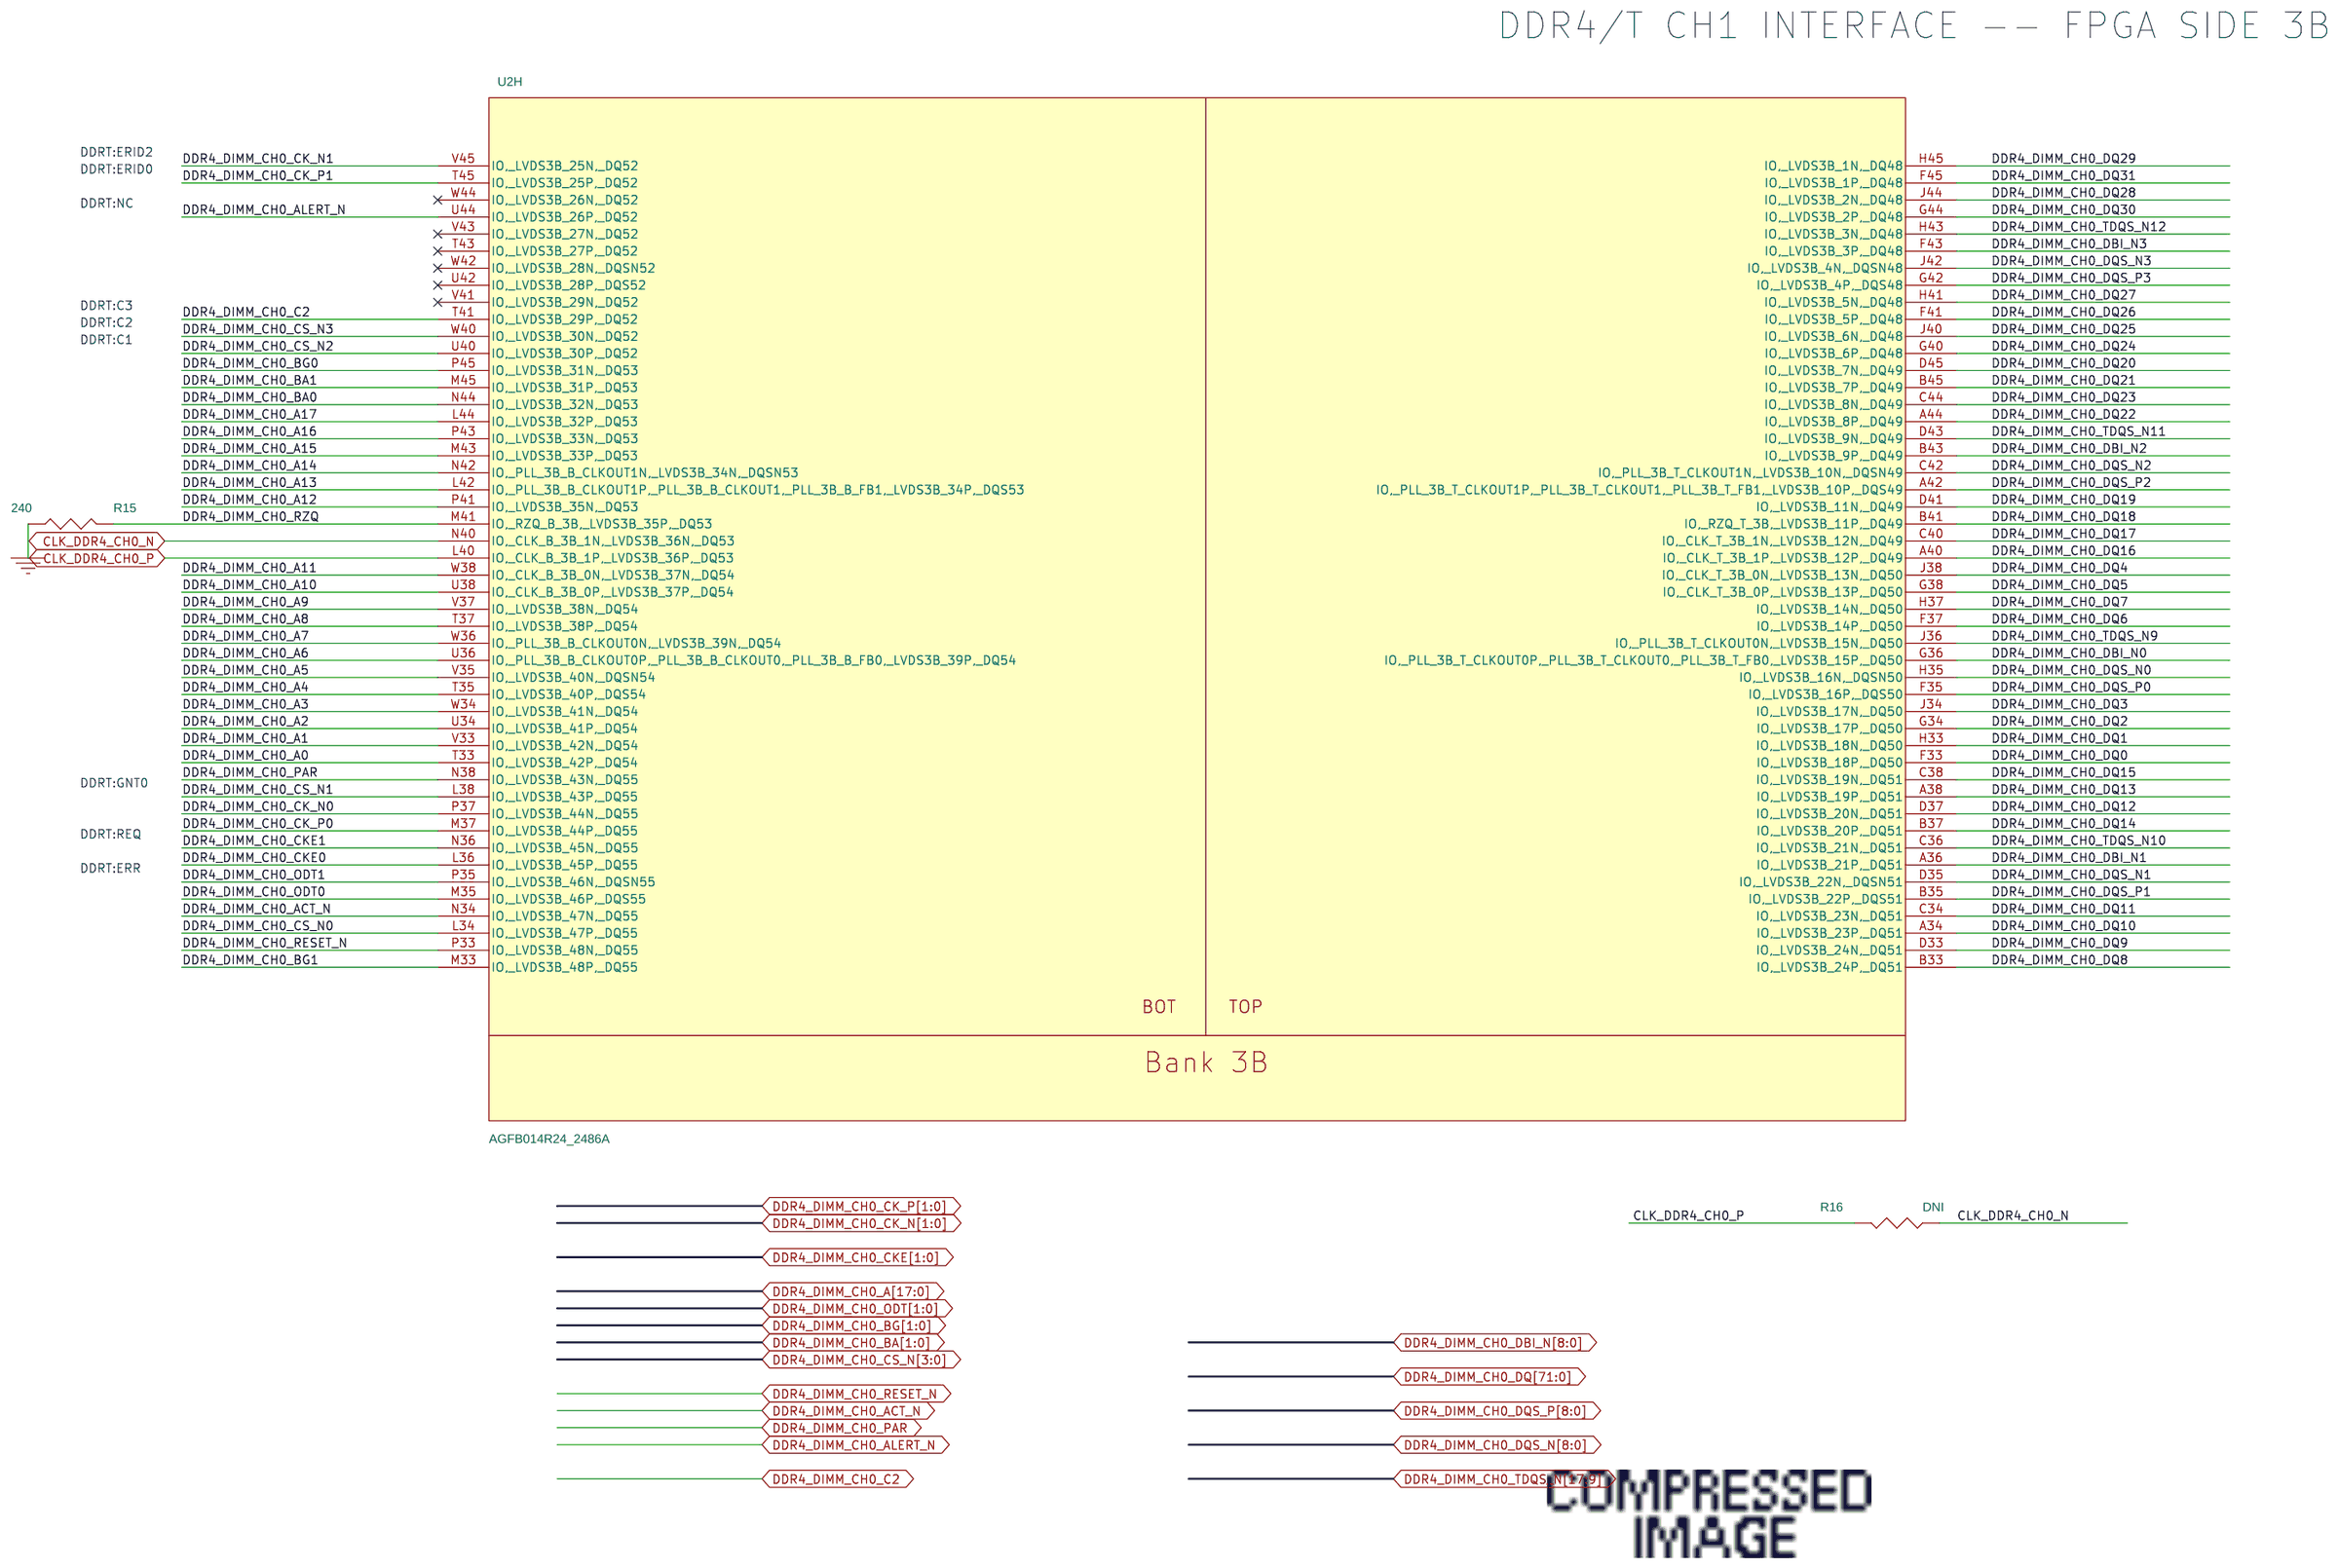
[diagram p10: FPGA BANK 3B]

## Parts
sheet DDR4/DDRT Single DIMM CH0
C1  1uF  [0402]
C2  0.1uF  [0402]
C3  0.1uF  [0402]
C4  10nF  [0402]
C5  0.1uF  [0402]
C6  10nF  [0402]
C7  0.1uF  [0402]
C8  10nF  [0402]
C9  0.1uF  [0402]
C10  10nF  [0402]
C11  0.1uF  [0402]
C12  10nF  [0402]
C13  0.1uF  [0402]
C14  10nF  [0402]
C15  0.1uF  [0402]
C16  100uF  [1206]
C17  1uF  [0402]
C18  0.1uF  [0402]
C19  0.1uF  [0402]
C20  100uF  [1206]
C21  100uF  [1206]
C22  10uF  [1210]
C23  10uF  [1210]
C24  0.1uF  [0402]
C25  0.1uF  [0402]
C26  0.1uF  [0402]
C27  10nF  [0402]
C28  10nF  [0402]
C29  10nF  [0402]
C31  0.1uF  [0402]
C32  100uF  [1206]
C33  10uF  [1210]
C34  0.1uF  [0402]
C35  10nF  [0402]
J1  DDR4x72x288  [DDR4DIMM_SMT]  (sections A,B)
R1  0  [1206]
R2  0  [1206]
R3  10.0K,DNI  [0402]
R4  10.0K  [0402]
R5  10.0K  [0402]
R6  10.0K  [0402]
R7  0  [0402]
R8  0  [0402]
R9  0  [0402]
R10  10.0K  [0402]
R11  DNI  [0402]
R12  DNI  [0402]
R13  DNI  [0402]
R14  0  [0603]
R789  10.0K  [0402]
U1  MAX3378E  [TSSOP-14]
sheet FPGA BANK 3B
R15  240  [0402]
R16  DNI  [0402]
sheet FPGA Gnd 2
U2  AGFB014R24_2486A  [FBGA2486A_HEX]  (sections A,B,C,D,E,F,G,H,I,J,K,L,M,N,O,P,Q,R,S,T,U,V,W,X)

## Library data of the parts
C1 C17 = CAP: CAP, X5R, 1UF, 20%, 10V, 0402,; IPN: H67656-001; Item Num: P03-15479R; Lead Free Status: Yes; Manufacturer: Murata; Manufacturer Part Num: GRM155R61A105KE15D; Num Pins: 2; Part Class: CAPACITORS; RoHS Compliant: Yes; Voltage: 10V
C2 C3 C5 C7 C9 C11 C13 C15 C18 C19 C24-C26 C31 C34 = CAP: CAPC,Y5V,0402,0.1UF,25V,+80/-20%; Dielectric: Y5V; IPN: K13560-001; Item Num: P03-15057R; LIFECYCLE_PHASE: Active; Lead Free Status: Lead Free; MFR_LIFECYCLE: Active; Manufacturer: Murata; Manufacturer Part Num: GRM155F51E104ZA01D; Num Pins: 2; PART_SUBCLASS: CAPACITORS; Part Class: CAPACITORS; RATED_VOLTAGE: 25V; RoHS Compliant: RoHS Compliant; Tolerance: +80%/-20%
C4 C6 C8 C10 C12 C14 C27-C29 C35 = Cap_10000PF_50V_0402: CAP - CERAMIC, 10nF, 0402, 50V, Y5V; IPN: K30697-001; IPN No: K30697-001; Item Num: P03-15058R; Manufacturer Part Num: GRM155F51H103Z
C16 C20 C21 C32 = CAP: CAP CER 100UF 6.3V X6T 1206; AGILE_LINK: http://sj-agile9app/Agile/PLMServlet?action=OpenEmailObject&classid=10000&objid=257560276; IPN: H65271-004; Item Num: P03-18002R; LIFECYCLE_PHASE: Active; Lead Free Status: Lead Free; MFR_LIFECYCLE: Active; Manufacturer: Murata; Manufacturer Part Num: GRM31CD80J107ME39L; Num Pins: 2; PART_SUBCLASS: CAPACITORS; RATED_VOLTAGE: 6.3V; RoHS Compliant: RoHS Compliant; TOLERANCE: 20%; Temperature Coefficient: X6T
C22 C23 C33 = CAP_10uF_+_-10%_25V_1210: CAP - CER, 10UF, 25V, 10%, X7R, 1210; Agile Part Description: CAP - CER, 10UF, 25V, 10%, X7R, 1210; IPN: G10603-003; Item Num: P03-15392R; Manufacturer Part Num: GRM32DR71E106KA12L
J1 = DDR4x72x288_1: CONN SMT DDR4 288POS VERT; COMPGROUP: DDR4_PINGPONG_DIMMA; IPN: K21528-001; Item Num: P23-38871R; Manufacturer: Molex Inc; Manufacturer Part Num: 787301002
R1 R2 = RESISTOR: RES SMD 0 OHM JUMPER 3/4W 1206; AGILE_LINK: http://sj-agile9app/Agile/PLMServlet?action=OpenEmailObject&classid=10000&objid=146548997; IPN: A93552-015; Item Num: P02-17994R; LIFECYCLE_PHASE: Active; Lead Free Status: No; MFR_LIFECYCLE: Active; Manufacturer: Vishay Dale; Manufacturer Part Num: CRCW12060000Z0EAHP; Num Pins: 2; PART_SUBCLASS: RESISTORS; POWER: 3/4W; RoHS Compliant: Yes; TOLERANCE: +/-1%
R3 = RESISTOR: RES,10.0K OHMS,1.0%,1/16W, 0402; AGILE_LINK: http://sj-agile9app/Agile/PLMServlet?action=OpenEmailObject&classid=10000&objid=146548997; IPN: A93548-034; Item Num: P02-11364R; LIFECYCLE_PHASE: Active; Lead Free Status: No; MFR_LIFECYCLE: Active; Manufacturer: Panasonic; Manufacturer Part Num: ERJ-2RKF1002X; Num Pins: 2; PART_SUBCLASS: RESISTORS; POWER: 1/16W; RESISTANCE: 10.0K; RoHS Compliant: Yes; TOLERANCE: +/-1%
R4-R6 R10 R789 = RESISTOR: RES,10.0K OHMS,1.0%,1/16W, 0402; AGILE_LINK: http://sj-agile9app/Agile/PLMServlet?action=OpenEmailObject&classid=10000&objid=146548997; IPN: A93548-034; Item Num: P02-11364R; LIFECYCLE_PHASE: Active; Lead Free Status: No; MFR_LIFECYCLE: Active; Manufacturer: Panasonic; Manufacturer Part Num: ERJ-2RKF1002X; Num Pins: 2; PART_SUBCLASS: RESISTORS; POWER: 1/16W; RoHS Compliant: Yes; TOLERANCE: +/-1%
R7-R9 = RES_0_OHM_5%_1_16W_0402_SMD: IPN: H30887-001
R11-R13 = RESISTOR: RES ZERO OHM 1/16W 5% 0402 SMD; IPN: H30887-001; Item Num: P02-14020R; Lead Free Status: No; Manufacturer: Panasonic; Manufacturer Part Num: ERJ-2GE0R00X; Num Pins: 2; Part Class: RESISTORS; Price: 0; RoHS Compliant: Yes; Tolerance: 5%
R14 = RESISTOR: RES - 0 OHM, 5% 0603 1/10W; IPN: E57868-001; Item Num: P02-14007R; Lead Free Status: No; Manufacturer: Panasonic; Manufacturer Part Num: ERJ-3GEY0R00V; Num Pins: 2; Part Class: RESISTORS; RoHS Compliant: Yes; Tolerance: 5%
U1 = MAX3378E_0: IC - QUAD LOW-VOLTAGE LEVEL TRANSLATOR, +/- 15KV, ESD-PROTECTED, 1UA, 16MBPS; IPN: C34337-001; Item Num: P01-13191R; Manufacturer: Maxim; Manufacturer Part Num: MAX3378EEUD
R15 = RESISTOR: RES - 240 OHM, 1/16W, 1%, 0402 SMD; IPN: K15783-001; Item Num: P02-15995R; LIFECYCLE_PHASE: Active; Lead Free Status: Lead Free; MFR_LIFECYCLE: Active; Manufacturer: Panasonic; Manufacturer Part Num: ERJ-2RKF2400X; Num Pins: 2; PART_SUBCLASS: RESISTORS; RoHS Compliant: RoHS Compliant
R16 = RESISTOR: RES,100 OHMS,1.0%,1/16W,0402; IPN: A36092-043; Item Num: P02-11381R; Lead Free Status: No; Manufacturer: Panasonic; Manufacturer Part Num: ERJ-2RKF1000X; Manufacturer's Part No.: ERJ-2RKF1000X; Num Pins: 2; Part Class: RESISTORS; Price: 0; RoHS Compliant: Yes
U2 = FM6_2486A_V1.5: IPN: 99AH52

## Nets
12V_G1: R1.1 R2.1 ; also on sheet 12 15 18 47 48 51 52 53 58
GND: C1.2 C2.2 C3.2 C4.2 C5.2 C6.2 C7.2 C8.2 C9.2 C10.2 C11.2 C12.2 C13.2 C14.2 C15.2 C16.1 C17.2 C18.2 C19.2 C20.1 C21.1 C22.2 C23.2 C24.2 C25.2 C26.2 C27.2 C28.2 C29.2 C31.2 C32.1 C33.2 C34.2 C35.2 J1.2(Vss) J1.4(Vss) J1.6(Vss) J1.9(Vss) J1.11(Vss) J1.13(Vss) J1.15(Vss) J1.17(Vss) J1.20(Vss) J1.22(Vss) J1.24(Vss) J1.26(Vss) J1.28(Vss) J1.31(Vss) J1.33(Vss) J1.35(Vss) J1.37(Vss) J1.39(Vss) J1.42(Vss) J1.44(Vss) J1.46(Vss) J1.48(Vss) J1.50(Vss) J1.53(Vss) J1.55(Vss) J1.57(Vss) J1.94(Vss) J1.96(Vss) J1.98(Vss) J1.101(Vss) J1.103(Vss) J1.105(Vss) J1.107(Vss) J1.109(Vss) J1.112(Vss) J1.114(Vss) J1.116(Vss) J1.118(Vss) J1.120(Vss) J1.123(Vss) J1.125(Vss) J1.127(Vss) J1.129(Vss) J1.131(Vss) J1.134(Vss) J1.136(Vss) J1.138(Vss) J1.147(Vss) J1.149(Vss) J1.151(Vss) J1.154(Vss) J1.156(Vss) J1.158(Vss) J1.160(Vss) J1.162(Vss) J1.165(Vss) J1.167(Vss) J1.169(Vss) J1.171(Vss) J1.173(Vss) J1.176(Vss) J1.178(Vss) J1.180(Vss) J1.182(Vss) J1.184(Vss) J1.187(Vss) J1.189(Vss) J1.191(Vss) J1.193(Vss) J1.195(Vss) J1.198(Vss) J1.200(Vss) J1.202(Vss) J1.239(Vss) J1.241(Vss) J1.243(Vss) J1.246(Vss) J1.248(Vss) J1.250(Vss) J1.252(Vss) J1.254(Vss) J1.257(Vss) J1.259(Vss) J1.261(Vss) J1.263(Vss) J1.265(Vss) J1.268(Vss) J1.270(Vss) J1.272(Vss) J1.274(Vss) J1.276(Vss) J1.279(Vss) J1.281(Vss) J1.283(Vss) R7.1 R8.1 R9.1 R11.1 R12.1 R13.1 R15.1 U1.7(GND) ; also on sheet 12 13 14 15 17 18 20 21 22 23 24 25 26 28 29 30 31 32 34 35 36 37 38 39 40 41 42 43 44 45 46 47 48 49 50 51 52 53 54 55 56 57 58 59 60 61 62 63 64 65 66
0p6V_VREF_DDR4_CH01: C18.1 C24.1 J1.146(Vrefca) ; also on sheet 12 34 62
0p6V_VTT_DDR4_CH01: C16.2 C17.1 C19.1 C29.1 C31.1 J1.77(Vtt) J1.221(Vtt) ; also on sheet 12 62
1p2V_DDR4_CH01: C3.1 C4.1 C5.1 C6.1 C7.1 C8.1 C9.1 C10.1 C11.1 C12.1 C13.1 C14.1 C15.1 C20.2 C21.2 C22.1 C23.1 C25.1 C26.1 C27.1 C28.1 J1.59(Vdd) J1.61(Vdd) J1.64(Vdd) J1.67(Vdd) J1.70(Vdd) J1.73(Vdd) J1.76(Vdd) J1.80(Vdd) J1.83(Vdd) J1.85(Vdd) J1.88(Vdd) J1.90(Vdd) J1.92(Vdd) J1.204(Vdd) J1.206(Vdd) J1.209(Vdd) J1.212(Vdd) J1.215(Vdd) J1.217(Vdd) J1.220(Vdd) J1.223(Vdd) J1.226(Vdd) J1.229(Vdd) J1.231(Vdd) J1.233(Vdd) J1.236(Vdd) R10.2 R789.2 U1.1(VL) U1.8(TSn) ; also on sheet 12 13 34 40 42 46 60 62 66
2p5V: C1.1 C2.1 C32.2 C33.1 C34.1 C35.1 J1.142(Vpp) J1.143(Vpp) J1.284(Vddspd) J1.286(Vpp) J1.287(Vpp) R3.2 R4.2 R5.2 R6.2 R14.1 U1.14(VCC) ; also on sheet 12 15 18 21 34 38 63
CLK_DDR4_CH0_N: R16.1 U2.N40(IO,_CLK_B_3B_1N,_LVDS3B_36N,_DQ53) ; also on sheet 38
CLK_DDR4_CH0_P: R16.2 U2.L40(IO,_CLK_B_3B_1P,_LVDS3B_36P,_DQ53) ; also on sheet 38
DDR4_CH0_EVENT_N: U1.2(IOVL1) ; also on sheet 13
DDR4_CH0_SAVE_N: U1.3(IOVL2) ; also on sheet 13
DDR4_DIMM0_EVENT_N: J1.78(EVENT_n) R4.1 U1.13(IOVCC1)
DDR4_DIMM0_SAVE_N: J1.230(SAVE_n/NC) R3.1 U1.12(IOVCC2)
DDR4_DIMM_CH0_A0: J1.79(A0) U2.T33(IO,_LVDS3B_42P,_DQ54)
DDR4_DIMM_CH0_A1: J1.72(A1) U2.V33(IO,_LVDS3B_42N,_DQ54)
DDR4_DIMM_CH0_A2: J1.216(A2) U2.U34(IO,_LVDS3B_41P,_DQ54)
DDR4_DIMM_CH0_A3: J1.71(A3) U2.W34(IO,_LVDS3B_41N,_DQ54)
DDR4_DIMM_CH0_A4: J1.214(A4) U2.T35(IO,_LVDS3B_40P,_DQS54)
DDR4_DIMM_CH0_A5: J1.213(A5) U2.V35(IO,_LVDS3B_40N,_DQSN54)
DDR4_DIMM_CH0_A6: J1.69(A6) U2.U36(IO,_PLL_3B_B_CLKOUT0P,_PLL_3B_B_CLKOUT0,_PLL_3B_B_FB0,_LVDS3B_39P,_DQ54)
DDR4_DIMM_CH0_A7: J1.211(A7) U2.W36(IO,_PLL_3B_B_CLKOUT0N,_LVDS3B_39N,_DQ54)
DDR4_DIMM_CH0_A8: J1.68(A8) U2.T37(IO,_LVDS3B_38P,_DQ54)
DDR4_DIMM_CH0_A9: J1.66(A9) U2.V37(IO,_LVDS3B_38N,_DQ54)
DDR4_DIMM_CH0_A10: J1.225(A10/AP) U2.U38(IO,_CLK_B_3B_0P,_LVDS3B_37P,_DQ54)
DDR4_DIMM_CH0_A11: J1.210(A11) U2.W38(IO,_CLK_B_3B_0N,_LVDS3B_37N,_DQ54)
DDR4_DIMM_CH0_A12: J1.65(A12) U2.P41(IO,_LVDS3B_35N,_DQ53)
DDR4_DIMM_CH0_A13: J1.232(A13) U2.L42(IO,_PLL_3B_B_CLKOUT1P,_PLL_3B_B_CLKOUT1,_PLL_3B_B_FB1,_LVDS3B_34P,_DQS53)
DDR4_DIMM_CH0_A14: J1.228(WE_n/A14) U2.N42(IO,_PLL_3B_B_CLKOUT1N,_LVDS3B_34N,_DQSN53)
DDR4_DIMM_CH0_A15: J1.86(CAS_n/A15) U2.M43(IO,_LVDS3B_33P,_DQ53)
DDR4_DIMM_CH0_A16: J1.82(RAS_n/A16) U2.P43(IO,_LVDS3B_33N,_DQ53)
DDR4_DIMM_CH0_A17: J1.234(A17/NC) U2.L44(IO,_LVDS3B_32P,_DQ53)
DDR4_DIMM_CH0_ACT_N: J1.62(ACT_n) U2.N34(IO,_LVDS3B_47N,_DQ55)
DDR4_DIMM_CH0_ALERT_N: J1.208(ALERT_n) R789.1 U2.U44(IO,_LVDS3B_26P,_DQ52)
DDR4_DIMM_CH0_BA0: J1.81(BA0) U2.N44(IO,_LVDS3B_32N,_DQ53)
DDR4_DIMM_CH0_BA1: J1.224(BA1) U2.M45(IO,_LVDS3B_31P,_DQ53)
DDR4_DIMM_CH0_BG0: J1.63(BG0) U2.P45(IO,_LVDS3B_31N,_DQ53)
DDR4_DIMM_CH0_BG1: J1.207(BG1) U2.M33(IO,_LVDS3B_48P,_DQ55)
DDR4_DIMM_CH0_C2: J1.235(C2/NC) U2.T41(IO,_LVDS3B_29P,_DQ52)
DDR4_DIMM_CH0_CK_N0: J1.75(CK0_c) U2.P37(IO,_LVDS3B_44N,_DQ55)
DDR4_DIMM_CH0_CK_N1: J1.219(CK1_c) U2.V45(IO,_LVDS3B_25N,_DQ52)
DDR4_DIMM_CH0_CK_P0: J1.74(CK0_t) U2.M37(IO,_LVDS3B_44P,_DQ55)
DDR4_DIMM_CH0_CK_P1: J1.218(CK1_t) U2.T45(IO,_LVDS3B_25P,_DQ52)
DDR4_DIMM_CH0_CKE0: J1.60(CKE0) R12.2 U2.L36(IO,_LVDS3B_45P,_DQ55)
DDR4_DIMM_CH0_CKE1: J1.203(CKE1) R13.2 U2.N36(IO,_LVDS3B_45N,_DQ55)
DDR4_DIMM_CH0_CS_N0: J1.84(S0_n) U2.L34(IO,_LVDS3B_47P,_DQ55)
DDR4_DIMM_CH0_CS_N1: J1.89(S1_n) U2.L38(IO,_LVDS3B_43P,_DQ55)
DDR4_DIMM_CH0_CS_N2: J1.93(S2_n/C0) U2.U40(IO,_LVDS3B_30P,_DQ52)
DDR4_DIMM_CH0_CS_N3: J1.237(S3_n/C1) U2.W40(IO,_LVDS3B_30N,_DQ52)
DDR4_DIMM_CH0_DBI_N0: J1.7(DQS9_t/DM0_n/DBI0_n) U2.G36(IO,_PLL_3B_T_CLKOUT0P,_PLL_3B_T_CLKOUT0,_PLL_3B_T_FB0,_LVDS3B_15P,_DQ50)
DDR4_DIMM_CH0_DBI_N1: J1.18(DQS10_t/DM1_n/DBI1_n) U2.A36(IO,_LVDS3B_21P,_DQ51)
DDR4_DIMM_CH0_DBI_N2: J1.29(DQS11_t/DM2_n/DBI2_n) U2.B43(IO,_LVDS3B_9P,_DQ49)
DDR4_DIMM_CH0_DBI_N3: J1.40(DQS12_t/DM3_n/DBI3_n) U2.F43(IO,_LVDS3B_3P,_DQ48)
DDR4_DIMM_CH0_DBI_N4: J1.99(DQS13_t/DM4_n/DBI4_n) U2.G50(IO,_PLL_3A_T_CLKOUT0P,_PLL_3A_T_CLKOUT0,_PLL_3A_T_FB0,_LVDS3A_15P,_DQ58)
DDR4_DIMM_CH0_DBI_N5: J1.110(DQS14_t/DM5_n/DBI5_n) U2.F57(IO,_LVDS3A_3P,_DQ56,_AVST_READY)
DDR4_DIMM_CH0_DBI_N6: J1.121(DQS15_t/DM6_n/DBI6_n) U2.B57(IO,_LVDS3A_9P,_DQ57,_SDM_MISSION_DATA20)
DDR4_DIMM_CH0_DBI_N7: J1.132(DQS16_t/DM7_n/DBI7_n) U2.T57(IO,_LVDS3A_27P,_DQ60)
DDR4_DIMM_CH0_DBI_N8: J1.51(DQS17_t/DM8_n/DBI8_n) U2.A50(IO,_LVDS3A_21P,_DQ59,_SDM_MISSION_DATA6)
DDR4_DIMM_CH0_DQ0: J1.5(DQ0) U2.F33(IO,_LVDS3B_18P,_DQ50)
DDR4_DIMM_CH0_DQ1: J1.150(DQ1) U2.H33(IO,_LVDS3B_18N,_DQ50)
DDR4_DIMM_CH0_DQ2: J1.12(DQ2) U2.G34(IO,_LVDS3B_17P,_DQ50)
DDR4_DIMM_CH0_DQ3: J1.157(DQ3) U2.J34(IO,_LVDS3B_17N,_DQ50)
DDR4_DIMM_CH0_DQ4: J1.3(DQ4) U2.J38(IO,_CLK_T_3B_0N,_LVDS3B_13N,_DQ50)
DDR4_DIMM_CH0_DQ5: J1.148(DQ5) U2.G38(IO,_CLK_T_3B_0P,_LVDS3B_13P,_DQ50)
DDR4_DIMM_CH0_DQ6: J1.10(DQ6) U2.F37(IO,_LVDS3B_14P,_DQ50)
DDR4_DIMM_CH0_DQ7: J1.155(DQ7) U2.H37(IO,_LVDS3B_14N,_DQ50)
DDR4_DIMM_CH0_DQ8: J1.16(DQ8) U2.B33(IO,_LVDS3B_24P,_DQ51)
DDR4_DIMM_CH0_DQ9: J1.161(DQ9) U2.D33(IO,_LVDS3B_24N,_DQ51)
DDR4_DIMM_CH0_DQ10: J1.23(DQ10) U2.A34(IO,_LVDS3B_23P,_DQ51)
DDR4_DIMM_CH0_DQ11: J1.168(DQ11) U2.C34(IO,_LVDS3B_23N,_DQ51)
DDR4_DIMM_CH0_DQ12: J1.14(DQ12) U2.D37(IO,_LVDS3B_20N,_DQ51)
DDR4_DIMM_CH0_DQ13: J1.159(DQ13) U2.A38(IO,_LVDS3B_19P,_DQ51)
DDR4_DIMM_CH0_DQ14: J1.21(DQ14) U2.B37(IO,_LVDS3B_20P,_DQ51)
DDR4_DIMM_CH0_DQ15: J1.166(DQ15) U2.C38(IO,_LVDS3B_19N,_DQ51)
DDR4_DIMM_CH0_DQ16: J1.27(DQ16) U2.A40(IO,_CLK_T_3B_1P,_LVDS3B_12P,_DQ49)
DDR4_DIMM_CH0_DQ17: J1.172(DQ17) U2.C40(IO,_CLK_T_3B_1N,_LVDS3B_12N,_DQ49)
DDR4_DIMM_CH0_DQ18: J1.34(DQ18) U2.B41(IO,_RZQ_T_3B,_LVDS3B_11P,_DQ49)
DDR4_DIMM_CH0_DQ19: J1.179(DQ19) U2.D41(IO,_LVDS3B_11N,_DQ49)
DDR4_DIMM_CH0_DQ20: J1.25(DQ20) U2.D45(IO,_LVDS3B_7N,_DQ49)
DDR4_DIMM_CH0_DQ21: J1.170(DQ21) U2.B45(IO,_LVDS3B_7P,_DQ49)
DDR4_DIMM_CH0_DQ22: J1.32(DQ22) U2.A44(IO,_LVDS3B_8P,_DQ49)
DDR4_DIMM_CH0_DQ23: J1.177(DQ23) U2.C44(IO,_LVDS3B_8N,_DQ49)
DDR4_DIMM_CH0_DQ24: J1.38(DQ24) U2.G40(IO,_LVDS3B_6P,_DQ48)
DDR4_DIMM_CH0_DQ25: J1.183(DQ25) U2.J40(IO,_LVDS3B_6N,_DQ48)
DDR4_DIMM_CH0_DQ26: J1.45(DQ26) U2.F41(IO,_LVDS3B_5P,_DQ48)
DDR4_DIMM_CH0_DQ27: J1.190(DQ27) U2.H41(IO,_LVDS3B_5N,_DQ48)
DDR4_DIMM_CH0_DQ28: J1.36(DQ28) U2.J44(IO,_LVDS3B_2N,_DQ48)
DDR4_DIMM_CH0_DQ29: J1.181(DQ29) U2.H45(IO,_LVDS3B_1N,_DQ48)
DDR4_DIMM_CH0_DQ30: J1.43(DQ30) U2.G44(IO,_LVDS3B_2P,_DQ48)
DDR4_DIMM_CH0_DQ31: J1.188(DQ31) U2.F45(IO,_LVDS3B_1P,_DQ48)
DDR4_DIMM_CH0_DQ32: J1.97(DQ32) U2.G48(IO,_LVDS3A_17P,_DQ58,_SDM_MISSION_DATA13)
DDR4_DIMM_CH0_DQ33: J1.242(DQ33) U2.F47(IO,_LVDS3A_18P,_DQ58,_SDM_MISSION_DATA11)
DDR4_DIMM_CH0_DQ34: J1.104(DQ34) U2.J48(IO,_LVDS3A_17N,_DQ58,_SDM_MISSION_DATA14)
DDR4_DIMM_CH0_DQ35: J1.249(DQ35) U2.H47(IO,_LVDS3A_18N,_DQ58,_SDM_MISSION_DATA12)
DDR4_DIMM_CH0_DQ36: J1.95(DQ36) U2.F51(IO,_LVDS3A_14P,_DQ58)
DDR4_DIMM_CH0_DQ37: J1.240(DQ37) U2.H51(IO,_LVDS3A_14N,_DQ58)
DDR4_DIMM_CH0_DQ38: J1.102(DQ38) U2.G52(IO,_CLK_T_3A_0P,_LVDS3A_13P,_DQ58)
DDR4_DIMM_CH0_DQ39: J1.247(DQ39) U2.J52(IO,_CLK_T_3A_0N,_LVDS3A_13N,_DQ58)
DDR4_DIMM_CH0_DQ40: J1.108(DQ40) U2.F55(IO,_LVDS3A_5P,_DQ56,_SDM_MISSION_DATA28)
DDR4_DIMM_CH0_DQ41: J1.253(DQ41) U2.G54(IO,_LVDS3A_6P,_DQ56,_SDM_MISSION_DATA26)
DDR4_DIMM_CH0_DQ42: J1.115(DQ42) U2.H55(IO,_LVDS3A_5N,_DQ56,_SDM_MISSION_DATA29)
DDR4_DIMM_CH0_DQ43: J1.260(DQ43) U2.J54(IO,_LVDS3A_6N,_DQ56,_SDM_MISSION_DATA27)
DDR4_DIMM_CH0_DQ44: J1.106(DQ44) U2.J58(IO,_LVDS3A_2N,_DQ56)
DDR4_DIMM_CH0_DQ45: J1.251(DQ45) U2.F59(IO,_LVDS3A_1P,_DQ56)
DDR4_DIMM_CH0_DQ46: J1.113(DQ46) U2.G58(IO,_LVDS3A_2P,_DQ56)
DDR4_DIMM_CH0_DQ47: J1.258(DQ47) U2.H59(IO,_LVDS3A_1N,_DQ56)
DDR4_DIMM_CH0_DQ48: J1.119(DQ48) U2.B55(IO,_RZQ_T_3A,_LVDS3A_11P,_DQ57,_SDM_MISSION_DATA16)
DDR4_DIMM_CH0_DQ49: J1.264(DQ49) U2.A54(IO,_CLK_T_3A_1P,_LVDS3A_12P,_DQ57)
DDR4_DIMM_CH0_DQ50: J1.126(DQ50) U2.D55(IO,_LVDS3A_11N,_DQ57,_SDM_MISSION_DATA17)
DDR4_DIMM_CH0_DQ51: J1.271(DQ51) U2.C54(IO,_CLK_T_3A_1N,_LVDS3A_12N,_DQ57)
DDR4_DIMM_CH0_DQ52: J1.117(DQ52) U2.D59(IO,_LVDS3A_8N,_DQ57,_SDM_MISSION_DATA23)
DDR4_DIMM_CH0_DQ53: J1.262(DQ53) U2.C58(IO,_LVDS3A_8P,_DQ57,_SDM_MISSION_DATA22)
DDR4_DIMM_CH0_DQ54: J1.124(DQ54) U2.F61(IO,_LVDS3A_7P,_DQ57,_SDM_MISSION_DATA24)
DDR4_DIMM_CH0_DQ55: J1.269(DQ55) U2.H61(IO,_LVDS3A_7N,_DQ57,_SDM_MISSION_DATA25)
DDR4_DIMM_CH0_DQ56: J1.130(DQ56) U2.V55(IO,_LVDS3A_29N,_DQ60)
DDR4_DIMM_CH0_DQ57: J1.275(DQ57) U2.T55(IO,_LVDS3A_29P,_DQ60)
DDR4_DIMM_CH0_DQ58: J1.137(DQ58) U2.W54(IO,_LVDS3A_30N,_DQ60)
DDR4_DIMM_CH0_DQ59: J1.282(DQ59) U2.U54(IO,_LVDS3A_30P,_DQ60)
DDR4_DIMM_CH0_DQ60: J1.128(DQ60) U2.W58(IO,_LVDS3A_26N,_DQ60)
DDR4_DIMM_CH0_DQ61: J1.273(DQ61) U2.T59(IO,_LVDS3A_25P,_DQ60)
DDR4_DIMM_CH0_DQ62: J1.135(DQ62) U2.U58(IO,_LVDS3A_26P,_DQ60)
DDR4_DIMM_CH0_DQ63: J1.280(DQ63) U2.V59(IO,_LVDS3A_25N,_DQ60)
DDR4_DIMM_CH0_DQ64: J1.49(CB0/NC) U2.A48(IO,_LVDS3A_23P,_DQ59,_SDM_MISSION_DATA2)
DDR4_DIMM_CH0_DQ65: J1.194(CB1/NC) U2.B47(IO,_LVDS3A_24P,_DQ59,_SDM_MISSION_DATA0)
DDR4_DIMM_CH0_DQ66: J1.56(CB2/NC) U2.C48(IO,_LVDS3A_23N,_DQ59,_SDM_MISSION_DATA3)
DDR4_DIMM_CH0_DQ67: J1.201(CB3/NC) U2.D47(IO,_LVDS3A_24N,_DQ59,_SDM_MISSION_DATA1)
DDR4_DIMM_CH0_DQ68: J1.47(CB4/NC) U2.C52(IO,_LVDS3A_19N,_DQ59,_SDM_MISSION_DATA10)
DDR4_DIMM_CH0_DQ69: J1.192(CB5/NC) U2.D51(IO,_LVDS3A_20N,_DQ59,_SDM_MISSION_DATA8)
DDR4_DIMM_CH0_DQ70: J1.54(CB6/NC) U2.B51(IO,_LVDS3A_20P,_DQ59,_SDM_MISSION_DATA_VALID)
DDR4_DIMM_CH0_DQ71: J1.199(CB7/NC) U2.A52(IO,_LVDS3A_19P,_DQ59,_SDM_MISSION_DATA9)
DDR4_DIMM_CH0_DQS_N0: J1.152(DQS0_c) U2.H35(IO,_LVDS3B_16N,_DQSN50)
DDR4_DIMM_CH0_DQS_N1: J1.163(DQS1_c) U2.D35(IO,_LVDS3B_22N,_DQSN51)
DDR4_DIMM_CH0_DQS_N2: J1.174(DQS2_c) U2.C42(IO,_PLL_3B_T_CLKOUT1N,_LVDS3B_10N,_DQSN49)
DDR4_DIMM_CH0_DQS_N3: J1.185(DQS3_c) U2.J42(IO,_LVDS3B_4N,_DQSN48)
DDR4_DIMM_CH0_DQS_N4: J1.244(DQS4_c) U2.H49(IO,_LVDS3A_16N,_DQSN58,_SDM_MISSION_CLK)
DDR4_DIMM_CH0_DQS_N5: J1.255(DQS5_c) U2.J56(IO,_LVDS3A_4N,_DQSN56,_SDM_MISSION_DATA31)
DDR4_DIMM_CH0_DQS_N6: J1.266(DQS6_c) U2.C56(IO,_PLL_3A_T_CLKOUT1N,_LVDS3A_10N,_DQSN57,_SDM_MISSION_DATA19)
DDR4_DIMM_CH0_DQS_N7: J1.277(DQS7_c) U2.W56(IO,_LVDS3A_28N,_DQSN60)
DDR4_DIMM_CH0_DQS_N8: J1.196(DQS8_c) U2.D49(IO,_LVDS3A_22N,_DQSN59,_SDM_MISSION_DATA5)
DDR4_DIMM_CH0_DQS_P0: J1.153(DQS0_t) U2.F35(IO,_LVDS3B_16P,_DQS50)
DDR4_DIMM_CH0_DQS_P1: J1.164(DQS1_t) U2.B35(IO,_LVDS3B_22P,_DQS51)
DDR4_DIMM_CH0_DQS_P2: J1.175(DQS2_t) U2.A42(IO,_PLL_3B_T_CLKOUT1P,_PLL_3B_T_CLKOUT1,_PLL_3B_T_FB1,_LVDS3B_10P,_DQS49)
DDR4_DIMM_CH0_DQS_P3: J1.186(DQS3_t) U2.G42(IO,_LVDS3B_4P,_DQS48)
DDR4_DIMM_CH0_DQS_P4: J1.245(DQS4_t) U2.F49(IO,_LVDS3A_16P,_DQS58,_SDM_MISSION_DATA15)
DDR4_DIMM_CH0_DQS_P5: J1.256(DQS5_t) U2.G56(IO,_LVDS3A_4P,_DQS56,_SDM_MISSION_DATA30)
DDR4_DIMM_CH0_DQS_P6: J1.267(DQS6_t) U2.A56(IO,_PLL_3A_T_CLKOUT1P,_PLL_3A_T_CLKOUT1,_PLL_3A_T_FB1,_LVDS3A_10P,_DQS57,_SDM_MISSION_DATA18)
DDR4_DIMM_CH0_DQS_P7: J1.278(DQS7_t) U2.U56(IO,_LVDS3A_28P,_DQS60)
DDR4_DIMM_CH0_DQS_P8: J1.197(DQS8_t) U2.B49(IO,_LVDS3A_22P,_DQS59,_SDM_MISSION_DATA4)
DDR4_DIMM_CH0_ODT0: J1.87(ODT0) U2.M35(IO,_LVDS3B_46P,_DQS55)
DDR4_DIMM_CH0_ODT1: J1.91(ODT1) U2.P35(IO,_LVDS3B_46N,_DQSN55)
DDR4_DIMM_CH0_PAR: J1.222(PARITY) U2.N38(IO,_LVDS3B_43N,_DQ55)
DDR4_DIMM_CH0_RESET_N: J1.58(RESET_n) R10.1 R11.2 U2.P33(IO,_LVDS3B_48N,_DQ55)
DDR4_DIMM_CH0_RZQ: R15.2 U2.M41(IO,_RZQ_B_3B,_LVDS3B_35P,_DQ53)
DDR4_DIMM_CH0_SA0: J1.139(SA0) R7.2
DDR4_DIMM_CH0_SA1: J1.140(SA1) R8.2
DDR4_DIMM_CH0_SA2: J1.238(SA2/RFU) R9.2
DDR4_DIMM_CH0_TDQS_N9: J1.8(DQS9_c) U2.J36(IO,_PLL_3B_T_CLKOUT0N,_LVDS3B_15N,_DQ50)
DDR4_DIMM_CH0_TDQS_N10: J1.19(DQS10_c) U2.C36(IO,_LVDS3B_21N,_DQ51)
DDR4_DIMM_CH0_TDQS_N11: J1.30(DQS11_c) U2.D43(IO,_LVDS3B_9N,_DQ49)
DDR4_DIMM_CH0_TDQS_N12: J1.41(DQS12_c) U2.H43(IO,_LVDS3B_3N,_DQ48)
DDR4_DIMM_CH0_TDQS_N13: J1.100(DQS13_c) U2.J50(IO,_PLL_3A_T_CLKOUT0N,_LVDS3A_15N,_DQ58)
DDR4_DIMM_CH0_TDQS_N14: J1.111(DQS14_c) U2.H57(IO,_LVDS3A_3N,_DQ56)
DDR4_DIMM_CH0_TDQS_N15: J1.122(DQS15_c) U2.D57(IO,_LVDS3A_9N,_DQ57,_SDM_MISSION_DATA21)
DDR4_DIMM_CH0_TDQS_N16: J1.133(DQS16_c) U2.V57(IO,_LVDS3A_27N,_DQ60)
DDR4_DIMM_CH0_TDQS_N17: J1.52(DQS17_c) U2.C50(IO,_LVDS3A_21N,_DQ59,_SDM_MISSION_DATA7)
DDR4_DIMM_SCL: U1.4(IOVL3) ; also on sheet 13
DDR4_DIMM_SDA: U1.5(IOVL4) ; also on sheet 13
DDR4D_SCL: J1.141(SCL) R5.1 U1.11(IOVCC3) ; also on sheet 12 15 18
DDR4D_SDA: J1.285(SDA) R6.1 U1.10(IOVCC4) ; also on sheet 12 15 18
N17328275: J1.1(12V/NC) J1.145(12V/NC) R1.2 R2.2
N17329090: J1.288(Vpp) R14.2

Not connected (* = marked no-connect by the designer): J1 144(RFU1)* 205(RFU2)* 227(RFU3)*; U1 6(NC0)* 9(NC1)*; U2 L48(IO,_LVDS3A_47P,_DQ63)* L50(IO,_LVDS3A_45P,_DQ63)* L52(IO,_LVDS3A_43P,_DQ63)* L54(IO,_CLK_B_3A_1P,_LVDS3A_36P,_DQ61)* L56(IO,_PLL_3A_B_CLKOUT1P,_PLL_3A_B_CLKOUT1,_PLL_3A_B_FB1,_LVDS3A_34P,_DQS61)* L58(IO,_LVDS3A_32P,_DQ61)* M47(IO,_LVDS3A_48P,_DQ63)* M49(IO,_LVDS3A_46P,_DQS63)* M51(IO,_LVDS3A_44P,_DQ63)* M55(IO,_RZQ_B_3A,_LVDS3A_35P,_DQ61)* M57(IO,_LVDS3A_33P,_DQ61)* M59(IO,_LVDS3A_31P,_DQ61)* N48(IO,_LVDS3A_47N,_DQ63)* N50(IO,_LVDS3A_45N,_DQ63)* N52(IO,_LVDS3A_43N,_DQ63)* N54(IO,_CLK_B_3A_1N,_LVDS3A_36N,_DQ61)* N56(IO,_PLL_3A_B_CLKOUT1N,_LVDS3A_34N,_DQSN61)* N58(IO,_LVDS3A_32N,_DQ61)* P47(IO,_LVDS3A_48N,_DQ63)* P49(IO,_LVDS3A_46N,_DQSN63)* P51(IO,_LVDS3A_44N,_DQ63)* P55(IO,_LVDS3A_35N,_DQ61)* P57(IO,_LVDS3A_33N,_DQ61)* P59(IO,_LVDS3A_31N,_DQ61)* T43(IO,_LVDS3B_27P,_DQ52)* T47(IO,_LVDS3A_42P,_DQ62)* T49(IO,_LVDS3A_40P,_DQS62)* T51(IO,_LVDS3A_38P,_DQ62)* U42(IO,_LVDS3B_28P,_DQS52)* U48(IO,_LVDS3A_41P,_DQ62)* U50(IO,_PLL_3A_B_CLKOUT0P,_PLL_3A_B_CLKOUT0,_PLL_3A_B_FB0,_LVDS3A_39P,_DQ62)* U52(IO,_CLK_B_3A_0P,_LVDS3A_37P,_DQ62)* V41(IO,_LVDS3B_29N,_DQ52)* V43(IO,_LVDS3B_27N,_DQ52)* V47(IO,_LVDS3A_42N,_DQ62)* V49(IO,_LVDS3A_40N,_DQSN62)* V51(IO,_LVDS3A_38N,_DQ62)* W42(IO,_LVDS3B_28N,_DQSN52)* W44(IO,_LVDS3B_26N,_DQ52)* W48(IO,_LVDS3A_41N,_DQ62)* W50(IO,_PLL_3A_B_CLKOUT0N,_LVDS3A_39N,_DQ62)* W52(IO,_CLK_B_3A_0N,_LVDS3A_37N,_DQ62)*

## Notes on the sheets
sheet 1
- REV
- DATE
- PAGES
- DESCRIPTION
- A1
- 25/05/2022
- All
- Changed Enpirion power modules with ADI parts
- B1
- 25/05/2022
- All
- IC LTM4668IY#PBF U66, U70 PGood 2,3,4 pins are made it NC & J22 modified as 2*2 connector
- PAGE
- DESCRIPTION
- PAGE
- DESCRIPTION
- 1
- Title, Notes, Rev. History
- 39
- Clock 2
- 2
- Block Diagram
- 40
- I2C and PMBUS
- 3
- Power Tree
- 41
- LEDs and PushButtons
- Board BOM : M75579-100
- 4
- Power Sequence Timing
- 42
- LEDs for QSFPDD
- PCB P/N :100-0330692-B1
- 5
- Clock Tree Diagram
- 43
- MAX10 - USB Blaster II -1
- 6
- I2C Diagram
- 44
- MAX10 - USB Blaster II -2
- 7
- JTAG Diagram
- 45
- PWR VCCA_PLL
- 8
- DDR4_DDR4 Pin Map
- 46
- MAX10  Power Control -1
- 9
- DDR4/DDRT Single DIMM CH0
- 47
- MAX10  Power Control -2
- 10
- FPGA BANK 3A
- 48
- Power inputs
- 11
- FPGA BANK 3B
- 49
- PWR 12V to 5V
- 12
- DDR4 Single DIMM CH1
- 50
- PWR 12V to 3.3V
- 13
- FPGA BANK 3C
- 51
- PWR VCC - 1
- 14
- FPGA BANK 3D
- 52
- PWR VCC - 2
- 15
- DDR4/DDRT Single DIMM CH2
- 53
- PWR VCC - 3
- 16
- FPGA BANK 2A
- 54
- PWR 1p8V
- 17
- FPGA BANK 2B
- 55
- PWR - 0p8V_VCCL_SDM
- 18
- DDR4/DDRT Single DIMM CH3
- 56
- PWR - 0p8V_VCCL_HPS
- 19
- FPGA BANK 2C
- 57
- PWR - IO_1p8V
- 20
- FPGA BANK 2D
- 58
- PWR - VCC_HSSI
- 21
- FPGA BANK 9A
- 59
- PWR - 1p2V_VCCR
- 22
- FPGA BANK 10A
- 60
- PWR - 1p2V_DDR4_CH01
- 23
- QSFPDD0
- 61
- PWR - 1p2V_DDR4_CH23
- 24
- QSFPDD1
- 62
- PWR - 0p6V_VTT/VREF
- 25
- PCIe End Point Edge Connector
- 63
- PWR - 2p5V
- 26
- FPGA Config SDM
- 64
- PWR - 1p1V_VCCH_GXER1
- 27
- FPGA BANK HPS
- 65
- PWR - Decouping Caps 1
- 28
- ETH PHY
- 66
- PWR - Decouping Caps 2
- 29
- UART
- 30
- Micro SD
- 31
- eMMC
- 32
- FPGA BANK NC DNU
- 33
- FPGA Power 1
- 34
- FPGA Power 2
- 35
- FPGA Gnd 1
- 36
- FPGA Gnd 2
- 37
- FPGA Gnd 3
- 38
- Clock 1
sheet 2
- System Block Diagram
sheet 4
- Power Sequence Timing
sheet 5
- Clock Tree
sheet 6
- I2C Diagram
sheet 7
- JTAG Block Diagrram
sheet 8
- DDR4/DDR-T DIMM Pin Map
- DDR-T DIMM Pin Map is Identical
  to standard DDR4 DIMM Pin Map
  except the DDR-T protocol
  repurposes five of these pins:
- CS1# (pin 89) : Grant, GNT# <0>  Input
- CKE1 (pin 203) : Request, REQ# <0> Output
- ODT1 (pin 91) : Error, ERR#      Output
- CLK1 (pin 218):Early Read ID, ERID<0>  Output
- CLK1# (pin 219):Early Read ID, ERID<1>  Output
sheet 9
- DDR4/DDRT Single DIMM CH0
- x72bit DIMM Only
- DDR4 DIMM IF
- I2C Addr: 0xA0
- Put caps on VDD pins which are close to DIMM A/C pins
sheet 10
- DDR4/T CH0 INTERFACE -- FPGA SIDE 3A
sheet 11
- DDR4/T CH1 INTERFACE -- FPGA SIDE 3B
- DDRT:ERID2
- DDRT:ERID0
- DDRT:NC
- DDRT:C3
- DDRT:C2
- DDRT:C1
- DDRT:GNT0
- DDRT:REQ
- DDRT:ERR
